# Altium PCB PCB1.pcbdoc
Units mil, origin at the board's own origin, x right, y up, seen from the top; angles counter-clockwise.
Board outline 2295 x 2720 mil, 4 copper layers (Top Layer, GND, PWR, Bottom Layer), stack 62.5 mil thick; 57 components, 63 nets, 259 pads, 97 vias.
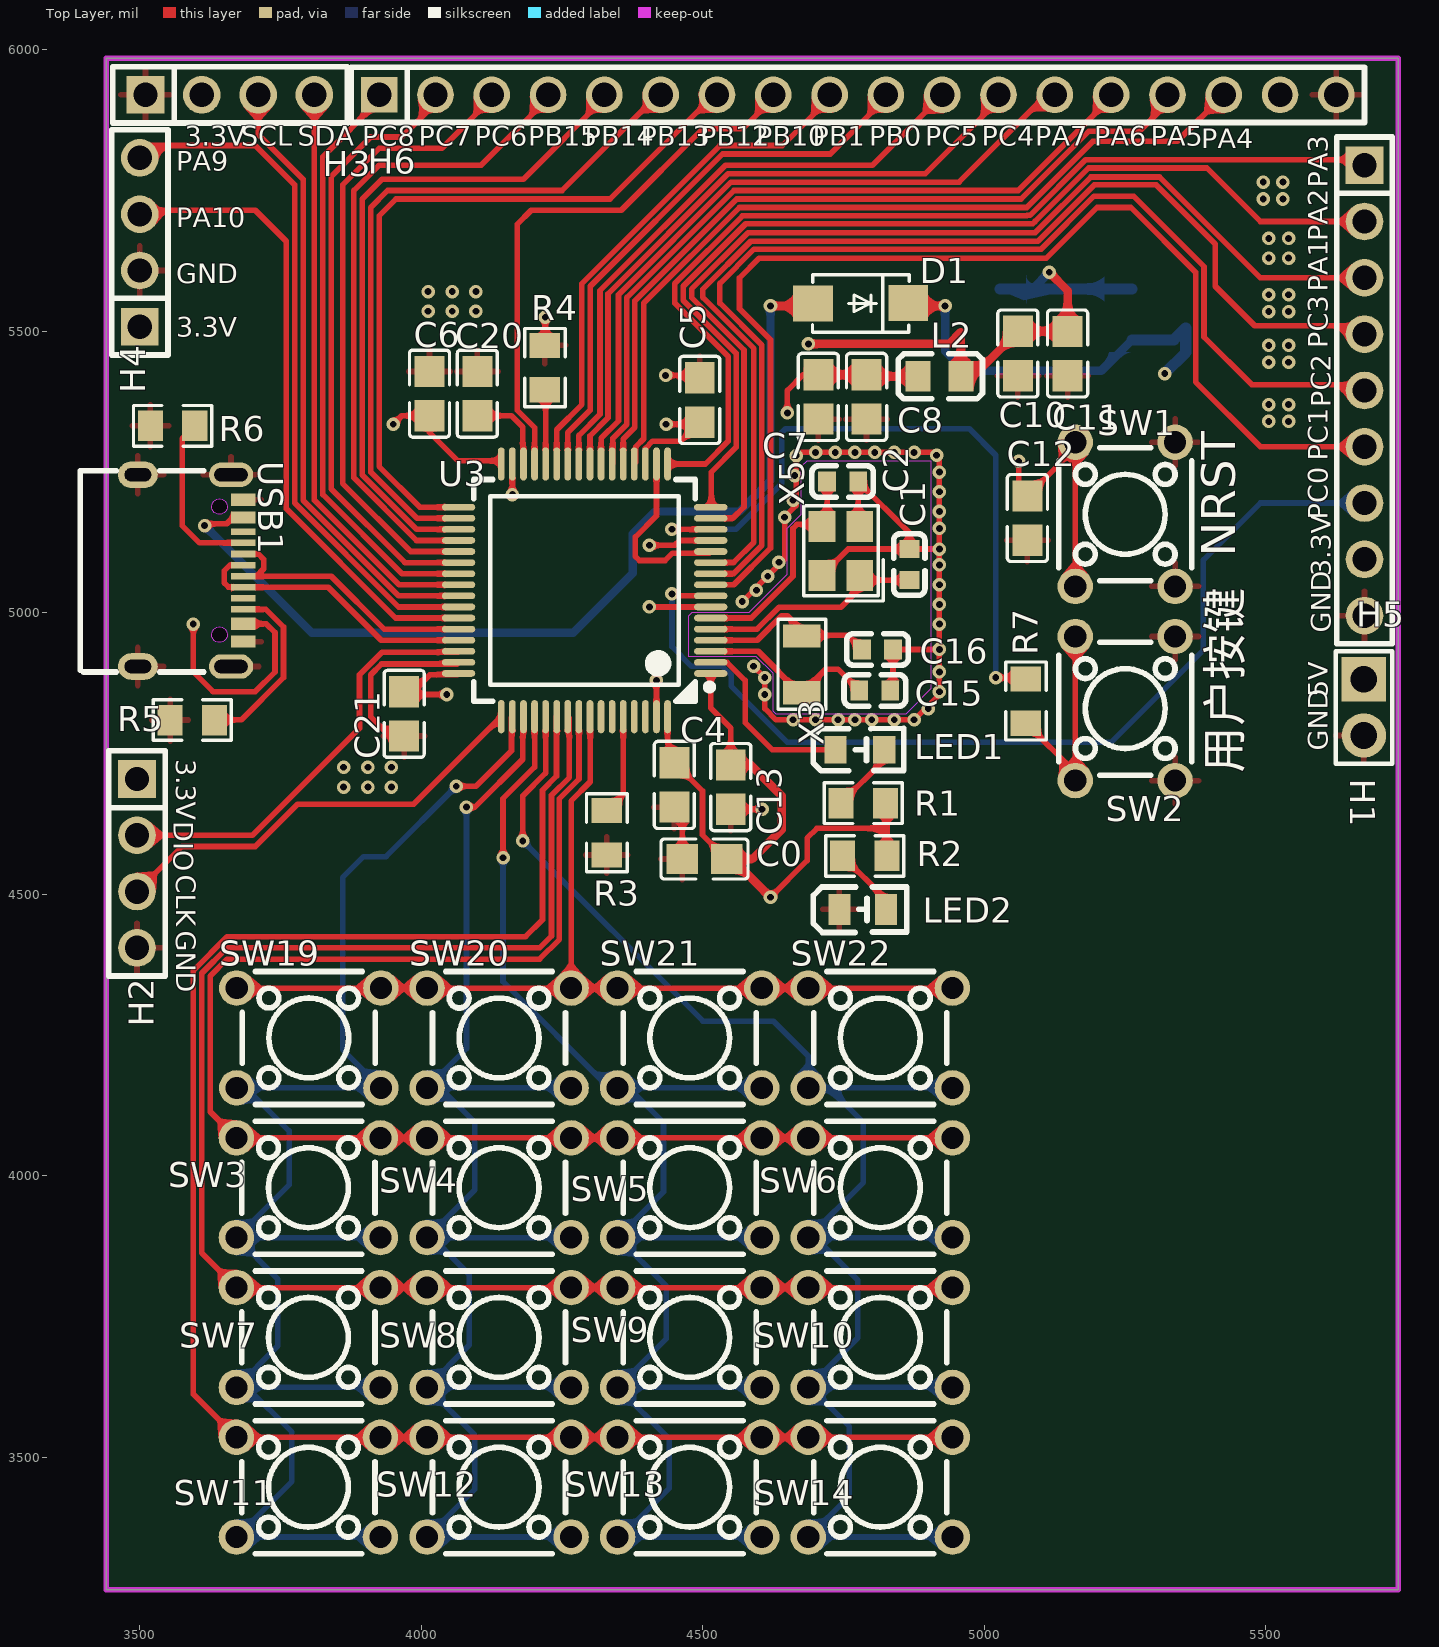
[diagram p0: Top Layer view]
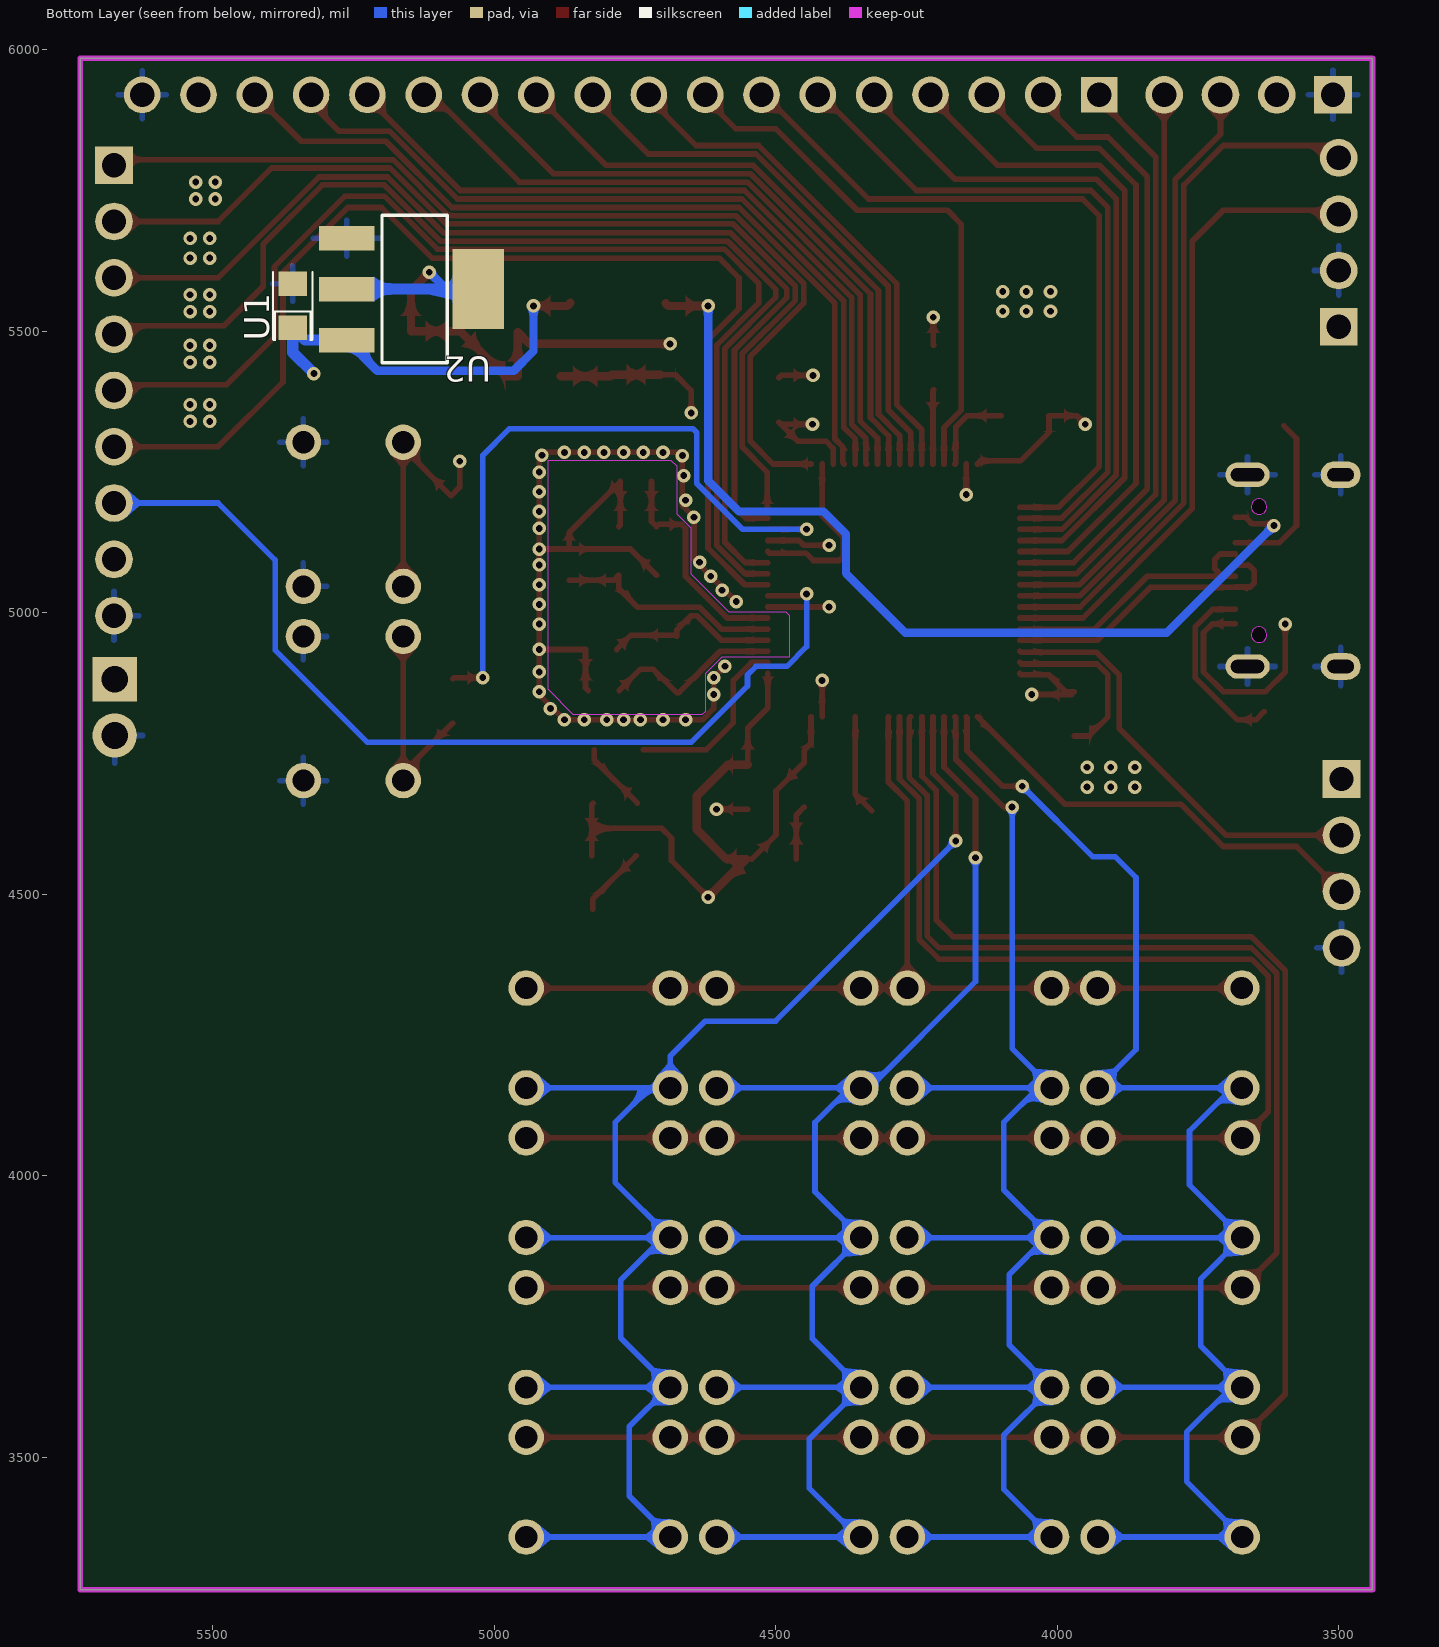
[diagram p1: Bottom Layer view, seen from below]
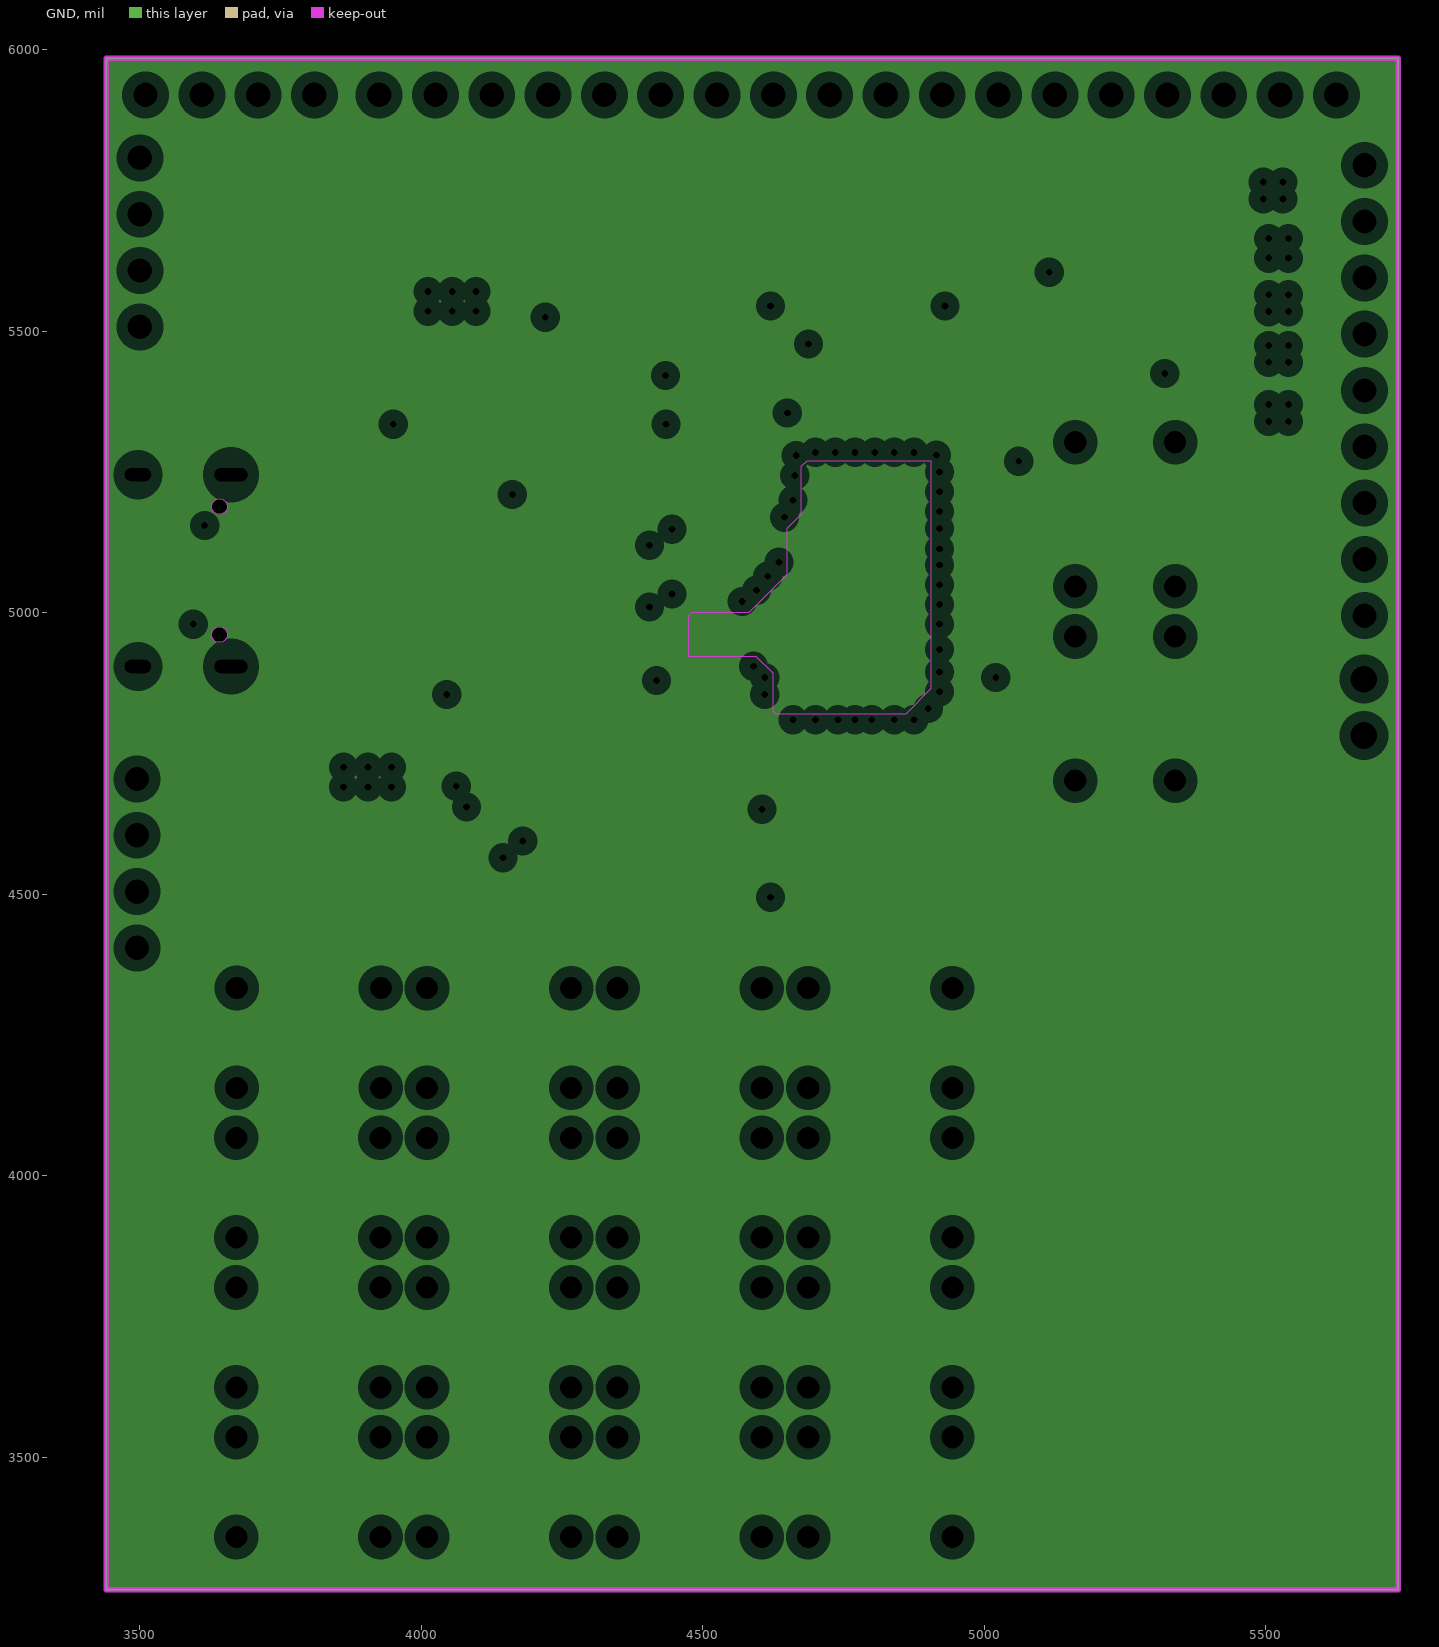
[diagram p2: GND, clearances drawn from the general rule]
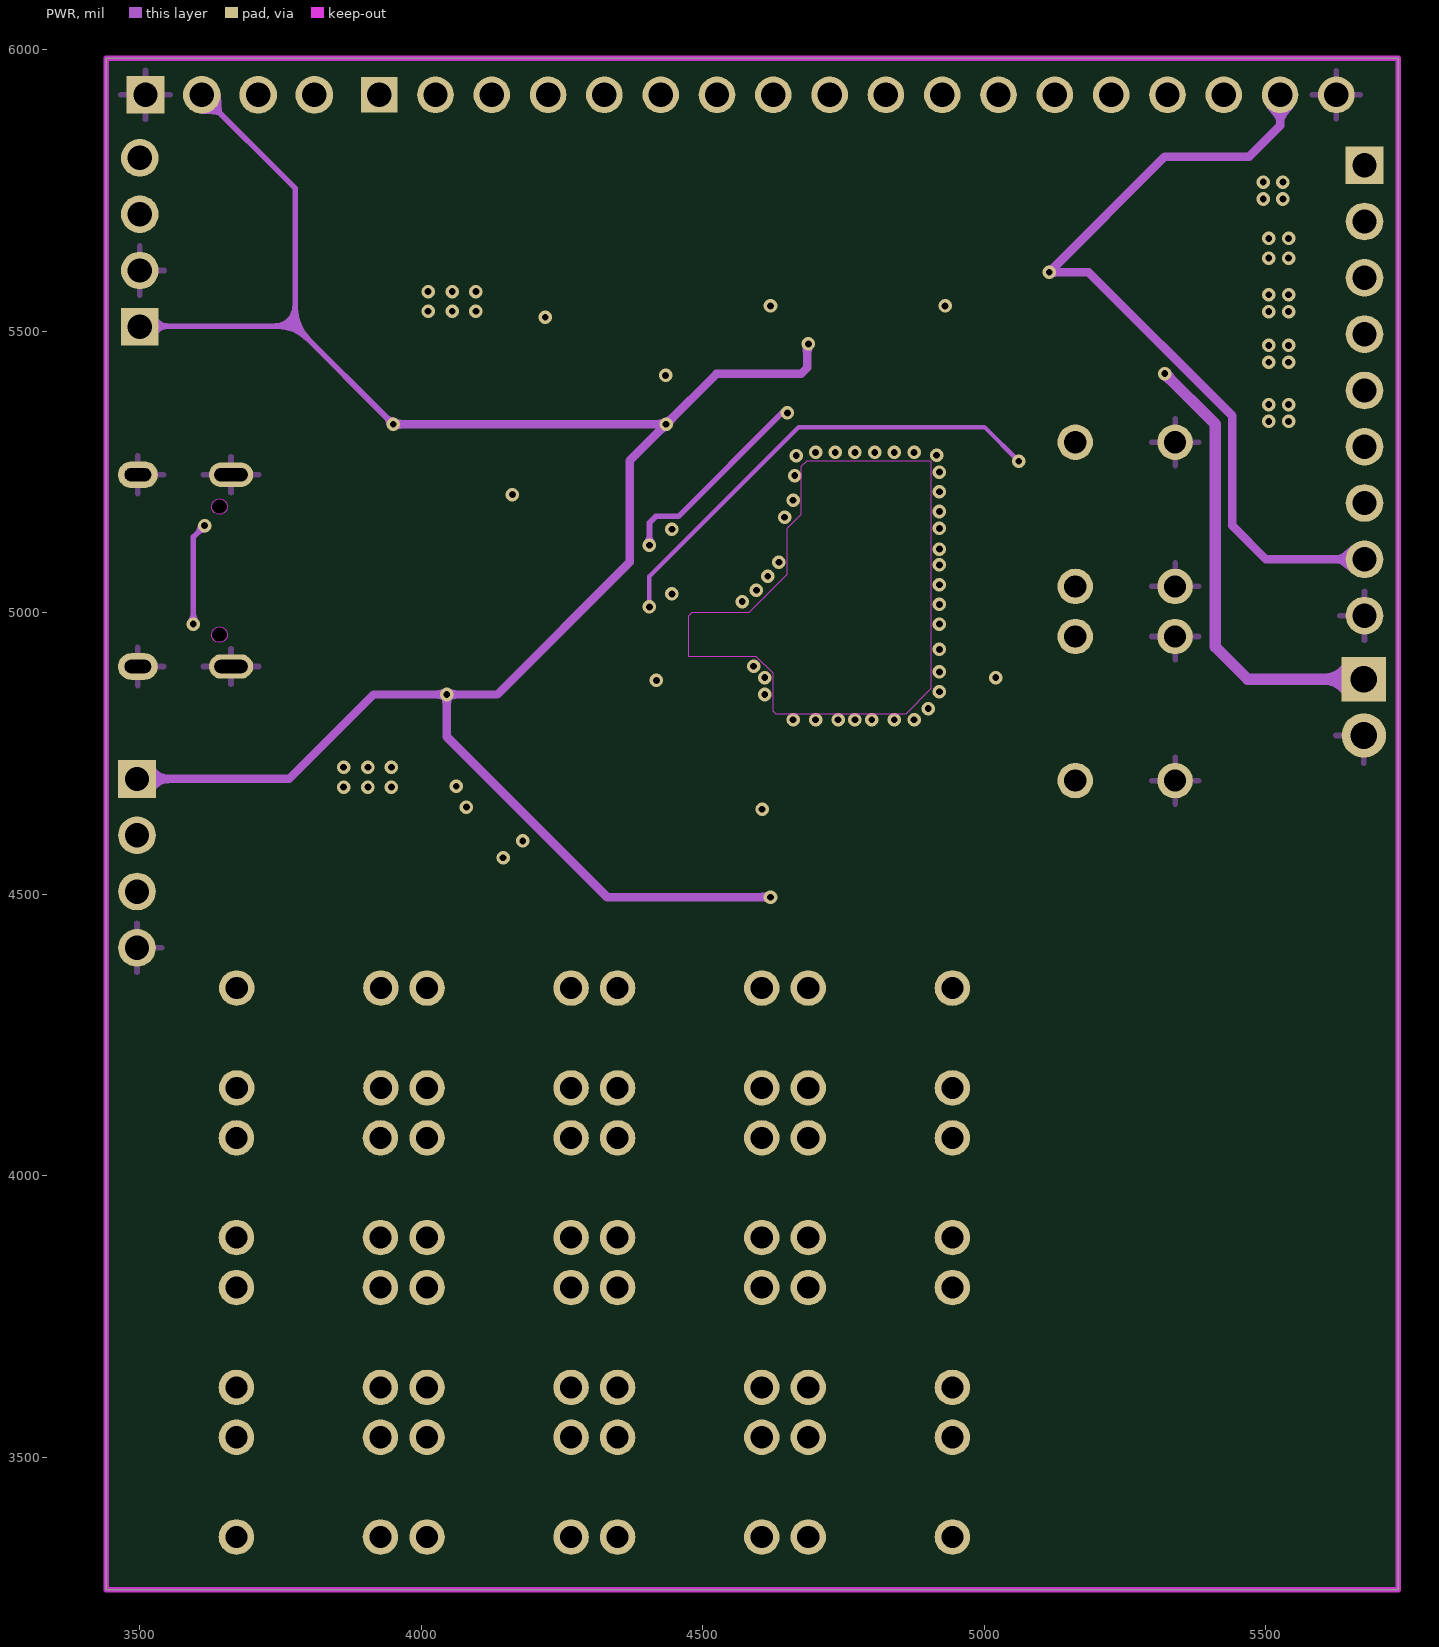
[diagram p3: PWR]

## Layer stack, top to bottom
Top Layer: signal copper 1.4
Dielectric1: surface 8.3, 7628 RC49% 8.6mil, Dk 0
GND: plane copper 0.6
Dielectric2: surface 41.9, 1.1mm H/HOZ Copper, Dk 0
PWR: signal copper 0.6
Dielectric3: surface 8.3, 7628 RC49% 8.6mil, Dk 0
Bottom Layer: signal copper 1.4

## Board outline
3440,5985 3440,3265 5735,3265 5735,5985

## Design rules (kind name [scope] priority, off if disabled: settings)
BoardOutlineClearance copperThickness1oz [All] p0: genericclearance=10 ignorepadtopadclearanceinfootprint=FALSE except(0: Arc-SplitContinuation Track-SplitContinuation SMDPad-SplitContinuation THPad-SplitContinuation Via-SplitContinuation Fill-SplitContinuation Poly-SplitContinuation Region-SplitContinuation Text-SplitContinuation)
BoardOutlineClearance copperThickness2oz [All] p0: genericclearance=10 ignorepadtopadclearanceinfootprint=FALSE except(0: Arc-SplitContinuation Track-SplitContinuation SMDPad-SplitContinuation THPad-SplitContinuation Via-SplitContinuation Fill-SplitContinuation Poly-SplitContinuation Region-SplitContinuation Text-SplitContinuation)
BoardOutlineClearance otherClearance [All] p0: genericclearance=10 ignorepadtopadclearanceinfootprint=FALSE except(0: Arc-SplitContinuation Track-SplitContinuation SMDPad-SplitContinuation THPad-SplitContinuation Via-SplitContinuation Fill-SplitContinuation Poly-SplitContinuation Region-SplitContinuation Text-SplitContinuation)
Clearance copperThickness1oz [All] p1: gap=7 ignorepadtopadclearanceinfootprint=FALSE
Clearance copperThickness2oz [All] p1: gap=7 ignorepadtopadclearanceinfootprint=FALSE
Clearance otherClearance [All] p1: gap=7 ignorepadtopadclearanceinfootprint=FALSE
DiffPairsRouting differentialPair [All] p1: maxuncoupledlength=10 minlimit=6 maxlimit=Infinity mostfreqgap=6 toplayer_minwidth=5 toplayer_prefwidth=10 toplayer_maxwidth=100 bottomlayer_minwidth=5 bottomlayer_prefwidth=10 bottomlayer_maxwidth=100 midlayer1_minwidth=5 midlayer1_prefwidth=10 midlayer1_maxwidth=100
PasteMaskExpansion pasteMaskExpansion [All] p1: expansion=0
PlaneConnect innerPlane [All] p1: planeconnectstyle=Relief reliefexpansion=20 reliefentries=4 reliefconductorwidth=10 reliefairgap=10
PolygonConnect copperRegion [All] p1: connectstyle=Relief reliefentries=4 reliefconductorwidth=10 polygonreliefangle="90 Angle" airgapwidth=10
RoutingVias viaSize [All] p1: viastyle="Through Hole" holewidth=12.0078 minholewidth=11.811 maxholewidth=248.0314 width=12.0078 minwidth=11.811 maxwidth=248.0314
SolderMaskExpansion solderMaskExpansion [IsVia] p1: useseparateexpansions=TRUE expansion=-1000 expansionbottom=-1000
SolderMaskExpansion solderMaskExpansion [All] p2: useseparateexpansions=TRUE expansion=2 expansionbottom=2
Width copperThickness1oz [All] p1: maxlimit=100 minlimit=5 preferedwidth=10
Width copperThickness2oz [All] p1: maxlimit=100 minlimit=8 preferedwidth=10

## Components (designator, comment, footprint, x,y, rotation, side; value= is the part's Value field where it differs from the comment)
C0 "4.7uF" C0805#1 4502.8,4562.8 r0 top
C1 "8pF" C0603#1 4866.5,5085.7 r270 top
C2 "8pF" C0603#2 4748.1,5233.3 r180 top
C4 "100nF" C0805#2 4449.4,4694.4 r90 top
C5 "100nF" C0805#1 4494.4,5378.1 r270 top
C6 "100nF" C0805#3 4014.4,5389.4 r270 top
C7 "100nF" C0805#2 4705,5383.5 r90 top
C8 "1uF" C0805#2 4790.6,5383.5 r90 top
C10 "100nF" C0805#3 5059.4,5460.6 r90 top
C11 "10uF" C0805#2 5147.6,5460.6 r90 top
C12 "100nF" C0805#2 5076.3,5168.4 r90 top
C13 "100nF" C0805#3 4549.4,4690.6 r90 top
C15 "1.5pF" C0603#1 4805.3,4862.2 r180 top
C16 "1.5pF" C0603#2 4810,4935 r180 top
C20 "4.7uF" C0805#3 4099.4,5389.4 r270 top
C21 "100nF" C0805#3 3969.4,4820.6 r90 top
D1 "SS14" SMA_L4.3-W2.6-LS5.0-FD 4780,5550 r0 top
H1 "PZ254V-11-02P" HDR-TH_2P-P2.54-V-M 5673.8,4832.2 r270 top
H2 "PZ254V-11-04P" HDR-TH_4P-P2.54-V-M 3495,4555 r270 top
H3 "PM254V-11-04-H85" HDR-TH_4P-P2.54-V-F 3660,5920 r0 top
H4 "PZ254V-11-04P" HDR-TH_4P-P2.54-V-M 3499.9,5658 r90 top
H5 "PZ254V-11-09P" HDR-TH_9P-P2.54-V-M 5675,5395 r270 top
H6 "PZ254-1-18-Z-8.5" HDR-TH_18P-P2.54-V-M 4775,5920 r0 top
L2 "CBW201209U102T" L0805 4920,5420 r180 top
LED1 "GL0805UB01" LED0805-RD_BLUE 4778.7,4757 r0 top
LED2 "GL0805UR01" LED0805-R-RD_RED 4783.7,4473.3 r0 top
R1 "1.5kΩ" R0805#1 4784.9,4662 r180 top
R2 "5.1kΩ" R0805#2 4787.4,4568.3 r180 top
R3 "10kΩ" R0805#1 4329.4,4609.4 r270 top
R4 "10kΩ" R0805#1 4219.4,5435.6 r90 top
R5 "5.1kΩ" R0805#1 3593,4809.6 r0 top
R6 "5.1kΩ" R0805#3 3558,5332.1 r180 top
R7 "330Ω" R0805#2 5073.6,4843.4 r270 top
SW1 "SH-6X6X4.3H-CJ" SW-TH_SH-6X6X4.3H-CJ#1 5250,5175 r90 top
SW2 "SH-6X6X4.3H-CJ" SW-TH_SH-6X6X4.3H-CJ#1 5250,4830 r90 top
SW3 "SH-6X6X4.3H-CJ" SW-TH_SH-6X6X4.3H-CJ#2 3799.3,3979 r0 top
SW4 "SH-6X6X4.3H-CJ" SW-TH_SH-6X6X4.3H-CJ#2 4137.9,3979 r0 top
SW5 "SH-6X6X4.3H-CJ" SW-TH_SH-6X6X4.3H-CJ#3 4476.5,3979 r0 top
SW6 "SH-6X6X4.3H-CJ" SW-TH_SH-6X6X4.3H-CJ#4 4815.1,3979 r0 top
SW7 "SH-6X6X4.3H-CJ" SW-TH_SH-6X6X4.3H-CJ#5 3799.3,3713.1 r0 top
SW8 "SH-6X6X4.3H-CJ" SW-TH_SH-6X6X4.3H-CJ#5 4137.9,3713.1 r0 top
SW9 "SH-6X6X4.3H-CJ" SW-TH_SH-6X6X4.3H-CJ#1 4476.5,3713.1 r0 top
SW10 "SH-6X6X4.3H-CJ" SW-TH_SH-6X6X4.3H-CJ#6 4815.1,3713.1 r0 top
SW11 "SH-6X6X4.3H-CJ" SW-TH_SH-6X6X4.3H-CJ#5 3799.3,3447.2 r0 top
SW12 "SH-6X6X4.3H-CJ" SW-TH_SH-6X6X4.3H-CJ#5 4137.9,3447.2 r0 top
SW13 "SH-6X6X4.3H-CJ" SW-TH_SH-6X6X4.3H-CJ#1 4476.5,3447.2 r0 top
SW14 "SH-6X6X4.3H-CJ" SW-TH_SH-6X6X4.3H-CJ#6 4815.1,3447.2 r0 top
SW19 "SH-6X6X4.3H-CJ" SW-TH_SH-6X6X4.3H-CJ#1 3800,4245 r0 top
SW20 "SH-6X6X4.3H-CJ" SW-TH_SH-6X6X4.3H-CJ#2 4137.9,4244.9 r0 top
SW21 "SH-6X6X4.3H-CJ" SW-TH_SH-6X6X4.3H-CJ#3 4476.5,4244.9 r0 top
SW22 "SH-6X6X4.3H-CJ" SW-TH_SH-6X6X4.3H-CJ#4 4815.1,4244.9 r0 top
U1 "10uF" CAP-SMD_L2.0-W1.3-FD 5357.6,5545.5 r90 bottom
U2 "AMS1117-3.3" SOT-223-3_L6.5-W3.4-P2.30-LS7.0-BR 5145,5575 r0 bottom
U3 "STM32F411RET6" LQFP-64_L10.0-W10.0-P0.50-LS12.0-BL 4290,5040 r90 top locked
USB1 "TYPE-C 16PIN 2MD(073)" USB-C-SMD_TYPE-C-16PIN-2MD-073 3590,5075 r270 top locked
X3 "32.768kHz" CRYSTAL-SMD_L3.2-W1.5-1 4675.8,4908.5 r270 top
X5 "25MHz" CRYSTAL-SMD_4P-L3.2-W2.5-BL 4745,5110 r90 top

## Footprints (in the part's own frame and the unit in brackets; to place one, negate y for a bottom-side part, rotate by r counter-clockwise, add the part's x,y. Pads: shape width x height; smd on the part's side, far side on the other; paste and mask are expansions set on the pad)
C0603#1 [mil]
  rect 31.5x35.4 smd: 1(-27.6,0) 2(27.5,0)
  silkscreen extent -55,-28 55,28
C0603#2 [mil]
  rect 31.5x35.4 smd: 1(-27.6,0) 2(27.6,0)
  silkscreen extent -55,-28 55,28
C0805#1 [mil]
  rect 55.5x53.1 smd paste-3937 mask+2: 1(-39.4,0) 2(39.4,0)
  silkscreen extent -77,-36 77,36
C0805#2 [mil]
  rect 55.5x53.1 smd paste-3937 mask+2: 1(-39.4,0) 2(39.3,0)
  silkscreen extent -77,-36 77,36
C0805#3 [mil]
  rect 55.5x53.1 smd paste-3937 mask+2: 1(-39.3,0) 2(39.4,0)
  silkscreen extent -77,-36 77,36
CAP-SMD_L2.0-W1.3-FD [mil]
  rect 43.3x51.2 smd paste+0 mask+2: 1(-39.4,0) 2(39.3,0)
  silkscreen extent -62,-35 60,35
CRYSTAL-SMD_4P-L3.2-W2.5-BL [mil]
  rect 55.1x47.2 smd: 1(-43.3,-33.5) 2(43.3,-33.5) 3(43.3,33.5) 4(-43.3,33.5)
  silkscreen extent -89,-75 80,66
CRYSTAL-SMD_L3.2-W1.5-1 [mil]
  rect 41.3x66.9 smd: 1(-50.2,0) 2(50.2,0)
  silkscreen extent -80,-43 80,42
HDR-TH_2P-P2.54-V-M [mil]
  rect 78.7x78.7 hole 47.2: 1(-50,0)
  round 78.7 hole 47.2: 2(50,0)
  silkscreen extent -100,-50 100,50
HDR-TH_4P-P2.54-V-F [mil]
  rect 66.9x66.9 hole 43.3: 1(-150,0)
  round 66.9 hole 43.3: 2(-50,0) 3(50,0) 4(150,0)
  silkscreen extent -208,-50 208,50
HDR-TH_4P-P2.54-V-M [mil]
  rect 66.9x66.9 hole 43.3: 1(-150,0)
  round 66.9 hole 43.3: 2(-50,0) 3(50,0) 4(150,0)
  silkscreen extent -200,-50 200,50
HDR-TH_9P-P2.54-V-M [mil]
  rect 66.9x66.9 hole 43.3: 1(-400,0)
  round 66.9 hole 43.3: 2(-300,0) 3(-200,0) 4(-100,0) 5(0,0) 6(100,0) 7(200,0) 8(300,0) 9(400,0)
  silkscreen extent -450,-49 450,49
HDR-TH_18P-P2.54-V-M [mil]
  rect 65x63 hole 43.3: 1(-850,0)
  round 65 hole 43.3: 2(-750,0) 3(-650,0) 4(-550,0) 5(-450,0) 6(-350,0) 7(-250,0) 8(-150,0) 9(-50,0) 10(50,0) 11(150,0) 12(250,0) 13(350,0) 14(450,0) 15(550,0) 16(650,0) 17(750,0) 18(850,0)
  silkscreen extent -900,-49 900,49
L0805 [mil]
  rect 44.6x54.2 smd paste-3937 mask+2: 1(-38,0) 2(38,0)
  silkscreen extent -77,-40 73,40
LED0805-R-RD_RED [mil]
  rect 39.4x55.1 smd: 1(41.3,0) 2(-41.4,0)
  silkscreen extent -88,-41 78,40
LED0805-RD_BLUE [mil]
  rect 39.4x49.2 smd: 1(-43.3,0) 2(43.3,0)
  silkscreen extent -83,-37 78,38
LQFP-64_L10.0-W10.0-P0.50-LS12.0-BL [mil]
  oval 11.8x59.1 smd: 1(-147.6,-223.9) 2(-127.9,-223.9) 3(-108.3,-223.9) 4(-88.6,-223.9) 5(-68.9,-223.9) 6(-49.2,-223.9) 7(-29.5,-223.9) 8(-9.8,-223.9) 9(9.8,-223.9) 10(29.5,-223.9) 11(49.2,-223.9) 12(68.9,-223.9) 13(88.6,-223.9) 14(108.3,-223.9) 15(127.9,-223.9) 16(147.6,-223.9) 33(147.6,223.9) 34(127.9,223.9) 35(108.3,223.9) 36(88.6,223.9) 37(68.9,223.9) 38(49.2,223.9) 39(29.5,223.9) 40(9.8,223.9) 41(-9.8,223.9) 42(-29.5,223.9) 43(-49.2,223.9) 44(-68.9,223.9) 45(-88.6,223.9) 46(-108.3,223.9) 47(-127.9,223.9) 48(-147.6,223.9)
  oval 59.1x11.8 smd: 17(224.4,-147.2) 18(224.4,-127.5) 19(224.4,-107.8) 20(224.4,-88.1) 21(224.4,-68.4) 22(224.4,-48.7) 23(224.4,-29.1) 24(224.4,-9.4) 25(224.4,10.3) 26(224.4,30) 27(224.4,49.7) 28(224.4,69.4) 29(224.4,89) 30(224.4,108.7) 31(224.4,128.4) 32(224.4,148.1) 49(-224.4,148.1) 50(-224.4,128.4) 51(-224.4,108.7) 52(-224.4,89) 53(-224.4,69.4) 54(-224.4,49.7) 55(-224.4,30) 56(-224.4,10.3) 57(-224.4,-9.4) 58(-224.4,-29.1) 59(-224.4,-48.7) 60(-224.4,-68.4) 61(-224.4,-88.1) 62(-224.4,-107.8) 63(-224.4,-127.5) 64(-224.4,-147.2)
  silkscreen extent -197,-228 197,197
R0805#1 [mil]
  rect 44.6x54.2 smd paste-3937 mask+2: 1(-39.3,0) 2(39.4,0)
  silkscreen extent -69,-36 69,36
R0805#2 [mil]
  rect 44.6x54.2 smd paste-3937 mask+2: 1(-39.4,0) 2(39.4,0)
  silkscreen extent -69,-36 69,36
R0805#3 [mil]
  rect 44.6x54.2 smd paste-3937 mask+2: 1(-39.4,0) 2(39.3,0)
  silkscreen extent -69,-36 69,36
SMA_L4.3-W2.6-LS5.0-FD [mil]
  rect 70.9x63.8 smd: 1(-84.6,-0.4) 2(84.6,0.4)
  silkscreen extent -85,-52 86,51
SOT-223-3_L6.5-W3.4-P2.30-LS7.0-BR [mil]
  rect 98.4x43.3 smd: 1(116.9,-90.6) 2(116.9,0) 3(116.9,90.6)
  rect 92.1x141.7 smd: 4(-116.9,0)
  silkscreen extent -62,-131 54,131
SW-TH_SH-6X6X4.3H-CJ#1 [mil]
  round 63 hole 39.4: A(-128,88.6) B(128,88.6) C(-128,-88.6) D(128,-88.6)
  silkscreen extent -118,-118 118,118
SW-TH_SH-6X6X4.3H-CJ#2 [mil]
  round 63 hole 39.4: A(-127.9,88.6) B(128,88.6) C(-127.9,-88.5) D(128,-88.5)
  silkscreen extent -118,-118 118,118
SW-TH_SH-6X6X4.3H-CJ#3 [mil]
  round 63 hole 39.4: A(-128,88.6) B(128,88.6) C(-128,-88.5) D(128,-88.5)
  silkscreen extent -118,-118 118,118
SW-TH_SH-6X6X4.3H-CJ#4 [mil]
  round 63 hole 39.4: A(-128,88.6) B(127.9,88.6) C(-128,-88.5) D(127.9,-88.5)
  silkscreen extent -118,-118 118,118
SW-TH_SH-6X6X4.3H-CJ#5 [mil]
  round 63 hole 39.4: A(-127.9,88.6) B(128,88.6) C(-127.9,-88.6) D(128,-88.6)
  silkscreen extent -118,-118 118,118
SW-TH_SH-6X6X4.3H-CJ#6 [mil]
  round 63 hole 39.4: A(-128,88.6) B(127.9,88.6) C(-128,-88.6) D(127.9,-88.6)
  silkscreen extent -118,-118 118,118
USB-C-SMD_TYPE-C-16PIN-2MD-073 [mil]
  oval 43.3x78.7 hole 23.6 slot 59.1 at 90 deg paste+0 mask+2: 13(-170.3,71.9) 14(170.3,71.9)
  oval 47.2x70.9 hole 23.6 slot 47.2 at 90 deg paste+0 mask+2: 13(-170.3,-93.5) 14(170.3,-93.5)
  rect 21.7x43.3 smd paste-3937 mask+2: A1B12(-126,93.5) A4B9(-94.5,93.5) B1A12(126,93.5) B4A9(94.5,93.5)
  rect 11.8x43.3 smd paste-3937 mask+2: A5(-49.2,93.5) A6(-9.8,93.5) A7(9.8,93.5) A8(49.2,93.5) B5(68.9,93.5) B6(29.5,93.5) B7(-29.5,93.5) B8(-68.9,93.5)
  Board Outline Layer lines w0.1: 113,37.6 116.2,37.8 119.2,38.7 122,40.3 124.3,42.5 126.1,45.2 127.2,48.2 127.6,51.4 127.2,54.6 126.1,57.6 124.3,60.2 122,62.4 119.2,64 116.2,64.9 113,65.1 109.8,64.6 106.9,63.3 104.3,61.4 102.3,58.9 100.8,56.1 100.1,53 100.1,49.8 100.8,46.7 102.3,43.8 104.3,41.4 106.9,39.4 109.8,38.2 113,37.6 ; -114.6,37.6 -111.4,37.8 -108.3,38.7 -105.5,40.3 -103.2,42.5 -101.5,45.2 -100.4,48.2 -100,51.4 -100.4,54.6 -101.5,57.6 -103.2,60.2 -105.5,62.4 -108.3,64 -111.4,64.9 -114.6,65.1 -117.7,64.6 -120.7,63.3 -123.2,61.4 -125.3,58.9 -126.7,56.1 -127.5,53 -127.5,49.8 -126.7,46.7 -125.3,43.8 -123.2,41.4 -120.7,39.4 -117.7,38.2 -114.6,37.6
  Board Outline Layer region: -100,51.4 -100.4,48.2 -101.5,45.2 -103.2,42.5 -105.5,40.3 -108.3,38.7 -111.4,37.8 -114.6,37.6 -117.7,38.2 -120.7,39.4 -123.2,41.4 -125.3,43.8 -126.7,46.7 -127.5,49.8 -127.5,53 -126.7,56.1 -125.3,58.9 -123.2,61.4 -120.7,63.3 -117.7,64.6 -114.6,65.1 -111.4,64.9 -108.3,64 -105.5,62.4 -103.2,60.2 -101.5,57.6 -100.4,54.6
  Board Outline Layer region: -100,51.4 -100.4,48.2 -101.5,45.2 -103.2,42.5 -105.5,40.3 -108.3,38.7 -111.4,37.8 -114.6,37.6 -117.7,38.2 -120.7,39.4 -123.2,41.4 -125.3,43.8 -126.7,46.7 -127.5,49.8 -127.5,53 -126.7,56.1 -125.3,58.9 -123.2,61.4 -120.7,63.3 -117.7,64.6 -114.6,65.1 -111.4,64.9 -108.3,64 -105.5,62.4 -103.2,60.2 -101.5,57.6 -100.4,54.6
  Board Outline Layer region: 127.6,51.4 127.2,48.2 126.1,45.2 124.3,42.5 122,40.3 119.2,38.7 116.2,37.8 113,37.6 109.8,38.2 106.9,39.4 104.3,41.4 102.3,43.8 100.8,46.7 100.1,49.8 100.1,53 100.8,56.1 102.3,58.9 104.3,61.4 106.9,63.3 109.8,64.6 113,65.1 116.2,64.9 119.2,64 122,62.4 124.3,60.2 126.1,57.6 127.2,54.6
  Board Outline Layer region: 127.6,51.4 127.2,48.2 126.1,45.2 124.3,42.5 122,40.3 119.2,38.7 116.2,37.8 113,37.6 109.8,38.2 106.9,39.4 104.3,41.4 102.3,43.8 100.8,46.7 100.1,49.8 100.1,53 100.8,56.1 102.3,58.9 104.3,61.4 106.9,63.3 109.8,64.6 113,65.1 116.2,64.9 119.2,64 122,62.4 124.3,60.2 126.1,57.6 127.2,54.6
  Multi-Layer board cut-out: -100,51.4 -100.4,48.2 -101.5,45.2 -103.2,42.5 -105.5,40.3 -108.3,38.7 -111.4,37.8 -114.6,37.6 -117.7,38.2 -120.7,39.4 -123.2,41.4 -125.3,43.8 -126.7,46.7 -127.5,49.8 -127.5,53 -126.7,56.1 -125.3,58.9 -123.2,61.4 -120.7,63.3 -117.7,64.6 -114.6,65.1 -111.4,64.9 -108.3,64 -105.5,62.4 -103.2,60.2 -101.5,57.6 -100.4,54.6
  Multi-Layer board cut-out: 127.6,51.4 127.2,48.2 126.1,45.2 124.3,42.5 122,40.3 119.2,38.7 116.2,37.8 113,37.6 109.8,38.2 106.9,39.4 104.3,41.4 102.3,43.8 100.8,46.7 100.1,49.8 100.1,53 100.8,56.1 102.3,58.9 104.3,61.4 106.9,63.3 109.8,64.6 113,65.1 116.2,64.9 119.2,64 122,62.4 124.3,60.2 126.1,57.6 127.2,54.6
  silkscreen extent -177,-196 180,24

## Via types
v1: diameter 24, hole 12, Top Layer to Bottom Layer, 97 vias

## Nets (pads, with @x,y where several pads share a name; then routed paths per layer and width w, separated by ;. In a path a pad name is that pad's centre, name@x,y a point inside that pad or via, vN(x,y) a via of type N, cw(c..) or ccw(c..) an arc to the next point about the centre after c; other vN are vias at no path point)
3.3V: C0.2 C4.2 C5.2 C6.2 C10.2 C11.2 C13.2 C21.2 H2.1 H3.2 H4.1 H5.8 H6.17 L2.1 R1.1 R2.1 U2.2 U2.4 U3.1 U3.19 U3.32 U3.48 U3.64 | length 8196.4
  Top Layer w10: v1(3950,5335) 3965,5350 C6.2 4014.4,5320.6 4065,5270 4136.3,5270 U3.32 ; v1(4045,4855) 3974.4,4855 C21.2 3985,4860 4015,4890 4063.7,4890 U3.48 ; U3.19 4397.8,5292.2 4410.5,5304.9 4460.6,5304.9 C5.2@4490.6,5335 ; v1(4434.5,5335) C5.2@4490.6,5335 ; U3.64 4437.2,4767.8 4449.4,4755.6 C4.2 4499.3,4683.8 4499.3,4605.7 C0.2 ; C5.2 C5.2@4490.6,5335 ; U3.1 4513.9,4831.1 4549.4,4795.6 C13.2 ; v1(4620,4495) 4685,4560 4685,4600 4702.3,4617.3 4826.8,4617.3 ; R1.1 4826.8,4659.5 4826.8,4617.3 ; R2.1 4826.8,4617.3
  Top Layer w15: C13.2 4585,4730 4640,4675 4640,4615 4587.8,4562.8 4552.2,4562.8 v1(4620,4495) ; v1(4687.4,5477.6) 4937,5477.6 4958,5498.7 L2.1 4979.4,5420 C10.2 ; C10.2@5059.4,5499.9 C11.2 5147.6,5572.4 v1(5115,5605)
  PWR w10: H4.1 3501.2,5509.3 3775.7,5509.3 ; H3.2 3775.7,5754.3 3775.7,5509.3 ; v1(3950,5335) 3775.7,5509.3
  PWR w15: H2.1 3765,4705 3915,4855 v1(4045,4855) ; v1(3950,5335) v1(4434.5,5335) ; v1(4620,4495) 4330,4495 4045,4780 v1(4045,4855) ; v1(4687.4,5477.6) 4685,5475.2 4685,5435 4674.4,5424.4 4523.9,5424.4 v1(4434.5,5335) ; H6.17 5525,5865 5470,5810 5320,5810 v1(5115,5605) 5185,5605 5440,5350 5440,5155 5500,5095 H5.8 ; v1(4045,4855) 4135,4855 4370,5090 4370,5270.5 v1(4434.5,5335)
  Bottom Layer w15: 5085,5575 v1(5115,5605)
  Bottom Layer w20: U2.4 5085,5575 U2.2
5V: D1.2 H1.1 U1.1 U2.3 | length 1528.3
  Top Layer w15: D1.2 4870,5545 v1(4930,5545)
  PWR w20: v1(5320,5425) 5410,5335 5410,4939.5 5467.3,4882.2 H1.1
  Bottom Layer w15: v1(4930,5545) 4930,5465 4965,5430 5207.5,5430 U2.3
  Bottom Layer w20: U2.3 5336,5484.4 U1.1 5357.6,5462.6 v1(5320,5425)
$1N58: LED1.2 R1.2 | length 126.7
  Top Layer w10: R1.2 4822,4738.5 LED1.2
$1N62: LED2.1 R2.2 | length 126.9
  Top Layer w10: R2.2 4825,4491.3 LED2.1
$1N82: R5.2 USB1.B5 | length 334.1
  Top Layer w10: R5.2@3632.4,4824.6 3647,4810 3680,4810 3755,4885 3755,4975 3723.9,5006.1 USB1.B5
$1N83: R6.1 USB1.A5 | length 307.6
  Top Layer w10: R6.1 3575,5309.7 3575,5155 3605.8,5124.2 USB1.A5
$1N95: R7.2 SW2.A SW2.B | length 380
  Top Layer w10: R7.2 SW2.A@5161.4,4716.2 ; SW2.A@5161.4,4702.1 SW2.A@5161.4,4716.2 ; SW2.B@5161.4,4957.9 SW2.A@5161.4,4716.2
$1N139: C20.2 U3.30 | length 155
  Top Layer w10: C20.2 4160,5350 4180,5330 4180,5265.7 U3.30
BOOT0: R3.1 U3.60 | length 178.9
  Top Layer w10: R3.1 4358.4,4677.8 U3.60
C1: SW19.A SW19.B SW20.A SW20.B SW21.A SW21.B SW22.A SW22.B U3.57 | length 1767.3
  Top Layer w10: SW19.A@3672.1,4333.6 3927.9,4333.6 4010,4333.6 SW20.B@4265.9,4333.6 ; U3.57 4300,4815 4300,4700 4265.9,4665.9 SW20.B@4265.9,4333.6 ; SW22.B@4943,4333.6 4687.1,4333.6 4604.4,4333.6 4348.6,4333.6 SW20.B@4265.9,4333.6
C2: SW3.A SW3.B SW4.A SW4.B SW5.A SW5.B SW6.A SW6.B U3.56 | length 2635.4
  Top Layer w10: U3.56 4280,4815.3 4280,4705 4245,4670 4245,4420 4210,4385 3655,4385 3625,4355 3625,4114 SW3.A SW3.B SW4.A SW4.B 4348.6,4067.6 4604.4,4067.6 SW6.A SW6.B
C3: SW7.A SW7.B SW8.A SW8.B SW9.A SW9.B SW10.A SW10.B U3.55 | length 2907.6
  Top Layer w10: U3.55 4262.8,4812.8 4262.8,4707.8 4231,4676 4231,4426 4210,4405 3655,4405 3610,4360 3610,3863.1 SW7.A SW7.B SW8.A SW8.B 4348.6,3801.7 4604.4,3801.7 SW10.A SW10.B
C4: SW11.A SW11.B SW12.A SW12.B SW13.A SW13.B SW14.A SW14.B U3.54 | length 3160.7
  Top Layer w10: U3.54 4240,4815.3 4240,4710 4215,4685 4215,4455 4185,4425 3655.2,4425 3595,4364.8 3595,3612.2 SW11.A SW11.B SW12.A SW12.B 4348.6,3535.8 4604.4,3535.8 SW14.A SW14.B
GND: C0.1 C1.1 C2.1 C4.1 C5.1 C6.1 C7.1 C8.1 C10.1 C11.1 C12.1 C13.1 C15.1 C16.1 C20.1 C21.1 H1.2 H2.4 H3.1 H4.2 H5.9 H6.18 LED2.2 R3.2 R4.2 R5.1 R6.2 SW1.C SW1.D SW2.C SW2.D U1.2 U2.1 U3.12 U3.18 U3.31 U3.47 U3.63 USB1.13 USB1.14 USB1.A1B12 USB1.B1A12 X5.2 X5.4 | length 3046
  Top Layer w10: C21.1 3943.7,4781.3 3910,4815 3910,4890 3929.2,4909.2 4063.3,4909.2 U3.47 ; v1(4161.6,5210) U3.31 ; R4.2 4220,5475.6 v1(4220,5525) ; U3.63 v1(4417.5,4880) ; U3.18 4417.5,5172.5 4380,5135 4380,5100 4387.1,5092.9 4432.9,5092.9 4446,5106 4483.2,5106 4483.3,5106.1 4511.1,5106.1 U3.12 ; v1(4433.6,5421.7) 4490.2,5421.7 C5.1 ; C4.1 4463.4,4641 C0.1 ; C13.1 v1(4605,4651.3) ; v1(4570,5020) v1(4615,5065) 4645,5095 v1(4645,5170) 4665.6,5190.6 v1(4665.6,5279.4) 4671.1,5285 v1(4700,5285) v1(4735,5285) v1(4770,5285) v1(4805,5285) v1(4840,5285) v1(4875,5285) 4910,5285 v1(4915,5280) 4920,5275 v1(4920,5250) v1(4920,5215) v1(4920,5180) v1(4920,5150) v1(4920,5113.3) ; v1(4590,4905) v1(4610,4885) v1(4610,4855) 4610,4830 4630,4810 v1(4660,4810) v1(4700,4810) v1(4740,4810) v1(4770,4810) v1(4800,4810) v1(4840,4810) v1(4875,4810) 4920,4855 v1(4920,4860) v1(4920,4895) v1(4920,4935) ; X5.4 4758.1,5113.3 C1.1 ; X5.2 4775.7,5156.1 C2.1 4866.5,5142.4 C1.1 ; C15.1 4837.6,4866.9 C16.1 v1(4920,4935) ; C1.1 v1(4920,5113.3) ; v1(4920,4935) v1(4920,4980) v1(4920,5015) v1(4920,5050) v1(4920,5085) v1(4920,5113.3)
  other v1: 3861.8,4690.7 3905,4690.7 3946.8,4690.7 3861.8,4725.7 3905,4725.7 3946.8,4725.7 4900,4830 4595,5040 4635,5090 4660,5200 4663,5243.8 5505,5340 5540,5340 5505,5370 5540,5370 5505,5445 5540,5445 5505,5475 5540,5475 5505,5535 5540,5535 4011.8,5535.7 4055,5535.7 4096.8,5535.7 5505,5565 5540,5565 4011.8,5570.7 4055,5570.7 4096.8,5570.7 5505,5630 5540,5630 5505,5665 5540,5665 5495,5735 5530,5735 5495,5765 5530,5765
NRST: C12.2 SW1.A SW1.B U3.7 | length 1398.2
  Top Layer w10: v1(4405,5010.5) U3.7 ; v1(5060.9,5269.1) 5060.9,5223.2 C12.2 SW1.B@5161.4,5292.8 ; SW1.A@5161.4,5047.1 SW1.B@5161.4,5292.8 ; SW1.B@5161.4,5302.9 SW1.B@5161.4,5292.8
  PWR w8: v1(4405,5010.5) 4405,5065 4670,5330 5000,5330 v1(5060.9,5269.1)
PA0: R7.1 U3.14 | length 1239.7
  Top Layer w10: v1(4445,5148.3) U3.14 ; v1(5020,4885) 5071.4,4885 R7.1
  Bottom Layer w10: v1(4445,5148.3) 4558.3,5148.3 4640,5230 4640,5320 4647.1,5327.1 4972.9,5327.1 5020,5280 v1(5020,4885)
PA1: H5.3 U3.15 | length 1844.6
  Top Layer w10: U3.15 4552.9,5167.9 4573,5188 4573,5466.8 4480,5559.8 4480,5575 4580,5675 5090,5675 5189.1,5774.1 5310.9,5774.1 5490,5595 H5.3
PA2: H5.2 U3.16 | length 1786.4
  Top Layer w10: U3.16 4515,5188.7 4515,5250 4559,5294 4559,5460.8 4557.5,5462.3 4557.5,5462.5 4465,5555 4465,5580 4576,5691 5085.6,5691 5089.6,5695 5090,5695 5185,5790 5395,5790 5490,5695 H5.2
PA3: H5.1 U3.17 | length 1764.2
  Top Layer w10: U3.17 4504.4,5264.4 4545,5305 4545,5455 4450,5550 4450,5585 4570,5705 5075,5705 5076,5706 5080.8,5706 5179.8,5805 5665,5805 H5.1
PA4: H6.16 U3.20 | length 1475.9
  Top Layer w10: U3.20 4380.9,5267.2 4380.9,5295.2 4395,5309.3 4395,5550 4565,5720 5075,5720 5192.5,5837.5 5342.5,5837.5 H6.16
PA5: H6.15 U3.21 | length 1403.3
  Top Layer w10: U3.21 4358.4,5308.6 4379,5329.2 4379,5554 4560,5735 5065,5735 5185,5855 5275,5855 5324.9,5904.9 H6.15@5324.9,5918.8
PA6: H6.14 U3.22 | length 1317.3
  Top Layer w10: U3.22 4340,5265.7 4340,5310 4365,5335 4365,5560 4555,5750 5060,5750 5224.9,5914.9 H6.14@5224.9,5918.8
PA7: H6.13 U3.23 | length 1234.8
  Top Layer w10: U3.23 4319.1,5310 4350,5340.9 4350,5565 4550,5765 4955,5765 5108.8,5918.8 H6.13@5124.9,5918.8
PA8: H3.3 U3.41 | length 1099.6
  Top Layer w10: H3.3 3710,5850 3790,5770 3790,5200 3959.8,5030.2 U3.41
PA9: H4.4 U3.42 | length 1245.7
  Top Layer w10: H4.4 3521.9,5830 3705,5830 3775,5760 3775,5195 3959.5,5010.5 U3.42
PA10: H4.3 U3.43 | length 1147.3
  Top Layer w10: H4.3 3506.9,5715 3705,5715 3760,5660 3760,5185 3954.2,4990.8 U3.43
PA11: U3.44 USB1.A7 USB1.B7 | length 520.7
  Top Layer w10: USB1.B7 3710.5,5104.5 3720,5095 3720,5078.2 3706.9,5065.2 USB1.A7 3683.7,5065 3840,5065 3933.9,4971.1 U3.44
PA12: U3.45 USB1.A6 USB1.B6 | length 517.7
  Top Layer w10: USB1.A6 3659.8,5084.8 3650,5075 3650,5053.1 3657.1,5046 3682.9,5046 USB1.B6 3834.5,5045.5 3928.6,4951.4 U3.45
PA13: H2.2 U3.46 | length 762
  Top Layer w10: H2.2 3700,4605 3890,4795 3890,4890 3930,4930 4064.3,4930 U3.46
PA14: H2.3 U3.49 | length 775.6
  Top Layer w10: H2.3 3575,4585 3705,4585 3780,4660 3986.3,4660 U3.49
PA15: SW3.C SW3.D SW7.C SW7.D SW11.C SW11.D SW19.C SW19.D U3.50 | length 2863.5
  Top Layer w10: v1(4062,4692) 4097,4692 4160,4755 4160,4814 U3.50
  Bottom Layer w10: SW7.C 3745,3698.2 3745,3816.9 SW3.C ; SW19.C@3672.1,4156.4 SW19.C@3688.6,4156.4 ; SW11.D SW11.C 3770,3457.2 3770,3545 3690.5,3624.5 SW7.D ; SW3.D SW3.C ; v1(4062,4692) 3937.1,4567.1 3897.1,4567.1 3860,4530 3860,4224.4 3927.9,4156.4 SW19.C@3688.6,4156.4 ; SW3.C 3765,3984.1 3765,4080 SW19.C@3688.6,4156.4
PB0: H6.10 U3.26 | length 1002.4
  Top Layer w10: U3.26 4260,5320 4300,5360 4300,5580 4535,5815 4726.1,5815 H6.10@4829.9,5918.8
PB1: H6.9 U3.27 | length 922.2
  Top Layer w10: U3.27 4240.3,5325.3 4285,5370 4285,5584.8 4530.2,5830 4641.1,5830 H6.9@4729.9,5918.8
PB2: R4.1 U3.28 | length 132.4
  Top Layer w10: R4.1 4220.6,5395 U3.28
PB6: U3.58
PB7: U3.59
PB8: U3.61
PB9: U3.62
PB10: H6.8 U3.29 | length 993.1
  Top Layer w10: U3.29 4201,5329 4170,5360 4170,5690 4195,5715 4355,5715 4500,5860 4571.1,5860 H6.8@4629.9,5918.8
PB12: H6.7 U3.33 | length 1309.5
  Top Layer w10: U3.33 3997.4,5187.6 3925,5260 3925,5705 3955,5735 4335,5735 4518.8,5918.8 H6.7@4529.9,5918.8
PB13: H6.6 U3.34 | length 1262.4
  Top Layer w10: U3.34 3992.1,5167.9 3910,5250 3910,5720 3940,5750 4250,5750 4418.8,5918.8 H6.6@4429.9,5918.8
PB14: H6.5 U3.35 | length 1212.2
  Top Layer w10: U3.35 3991.7,5148.3 3895,5245 3895,5735 3930,5770 4181.1,5770 H6.5@4329.9,5918.8
PB15: H6.4 U3.36 | length 1162.1
  Top Layer w10: U3.36 3991.4,5128.6 3880,5240 3880,5750 3925,5795 4106.1,5795 H6.4@4229.9,5918.8
PC0: H5.7 U3.8 | length 1745.7
  Top Layer w10: v1(4445,5033.5) 4448.3,5030.2 U3.8
  Bottom Layer w10: v1(4445,5033.5) 4445,4940 4480,4905 4535,4905 4550,4890 4550,4870 4650,4770 5225,4770 5388.8,4933.8 5388.8,5093.8 5490,5195 H5.7
PC1: H5.6 U3.9 | length 2087.9
  Top Layer w10: U3.9 4554.8,5049.8 4620,5115 4620,5485 4565,5540 4565,5595 4600,5630 5110,5630 5200,5720 5260,5720 5375,5605 5375,5410 5490,5295 H5.6
PC2: H5.5 U3.10 | length 2032.9
  Top Layer w10: U3.10 4554.5,5069.5 4602.5,5117.5 4602.5,5117.7 4604.4,5119.6 4604.4,5475.6 4530,5550 4530,5585 4591,5646 5100.8,5646 5194.8,5740 5265,5740 5390,5615 5390,5490 5475,5405 5665,5405 H5.5
PC3: H5.4 U3.11 | length 1983.9
  Top Layer w10: U3.11 4554.2,5089.2 4590.4,5125.4 4590.4,5469.6 4500,5560 4500,5575 4585,5660 5095,5660 5195,5760 5305,5760 5410,5655 5410,5580 5480,5510 5660,5510 H5.4
PC4: H6.12 U3.24 | length 1165.4
  Top Layer w10: U3.24 4299.4,5314.4 4330,5345 4330,5345.5 4331.4,5346.8 4331.4,5566.4 4545,5780 4895,5780 H6.12@5035,5920
PC5: H6.11 U3.25 | length 1074.6
  Top Layer w10: U3.25 4279.7,5315 4317.3,5352.7 4317.3,5572.3 4540,5795 4801.1,5795 H6.11@4924.9,5918.8
PC6: H6.3 U3.37 | length 1121.9
  Top Layer w10: U3.37 3981.1,5108.9 3860,5230 3860,5760 3925,5825 4036.1,5825 H6.3@4129.9,5918.8
PC7: H6.2 U3.38 | length 1087.9
  Top Layer w10: H6.2@4024.9,5918.8 4024.9,5904.9 3965,5845 3910,5845 3840,5775 3840,5220 3970.8,5089.2 U3.38
PC8: H6.1 U3.39 | length 1049.5
  Top Layer w10: H6.1@3924.9,5918.8 3924.9,5909.9 3825,5810 3825,5210 3965.5,5069.5 U3.39
PC9: H3.4 U3.40 | length 1038.3
  Top Layer w10: H3.4 3810,5200 3960.2,5049.8 U3.40
PC10: SW4.C SW4.D SW8.C SW8.D SW12.C SW12.D SW20.C SW20.D U3.51 | length 2725.9
  Top Layer w10: v1(4080,4655) 4095,4655 4180,4740 4180,4814.3 U3.51
  Bottom Layer w10: SW20.C 4080,4226.4 v1(4080,4655) ; SW12.D SW12.C 4095,3443.7 4095,3539.5 SW8.C ; SW8.D SW8.C ; SW4.D SW4.C@4019.5,3890.5 ; SW20.D 4033.6,4156.4 4095,4095 4095,3975.5 SW4.C SW4.C@4019.5,3890.5 ; SW8.C 4085,3699.6 4085,3825 SW4.C@4019.5,3890.5
PC11: SW5.C SW5.D SW9.C SW9.D SW13.C SW13.D SW21.C SW21.D U3.52 | length 2780.8
  Top Layer w10: v1(4145,4565) 4145,4670 4201,4726 U3.52
  Bottom Layer w10: v1(4145,4565) 4145,4345 4333.6,4156.4 SW21.C@4348.6,4156.4 ; SW13.C@4348.6,3358.6 SW13.C@4353.6,3358.6 ; SW13.D@4604.4,3358.6 SW13.C@4353.6,3358.6 ; SW9.D@4604.4,3624.5 SW9.C@4348.6,3624.5 ; SW5.D@4604.4,3890.5 SW5.C@4348.6,3890.5 ; SW21.D@4604.4,4156.4 4368.6,4156.4 4430,4095 4430,3971.9 SW5.C@4348.6,3890.5 ; SW9.C@4348.6,3624.5 4435,3711 4435,3804 SW5.C@4348.6,3890.5 ; SW9.C@4348.6,3624.5 4440,3533.1 4440,3445 SW13.C@4353.6,3358.6
PC12: SW6.C SW6.D SW10.C SW10.D SW14.C SW14.D SW22.C SW22.D U3.53 | length 2973.4
  Top Layer w10: v1(4180,4595) 4180,4675 4220.6,4715.6 U3.53
  Bottom Layer w10: v1(4180,4595) 4500,4275 4625,4275 4687.1,4212.9 SW22.C 4723.6,4156.4 ; SW14.D SW14.C 4760,3431.5 4760,3555 SW10.C@4690.5,3624.5 ; SW10.D SW10.C@4690.5,3624.5 ; SW6.D SW6.C@4699.5,3890.5 ; SW22.D 4723.6,4156.4 ; SW10.C@4690.5,3624.5 SW10.C 4775,3712.4 4775,3815 SW6.C@4699.5,3890.5 ; SW6.C@4699.5,3890.5 SW6.C 4785,3988.3 4785,4095 4723.6,4156.4
PC13: LED1.1 U3.2 | length 329.7
  Top Layer w10: U3.2 4542.9,4912.1 4575,4880 4575,4805 4623,4757 LED1.1
PC14: C15.2 U3.3 X3.2 | length 327.2
  Top Layer w10: U3.3 4598.3,4931.7 4671.7,4858.3 X3.2 4717.5,4900 4740,4900 C15.2
PC15: C16.2 U3.4 X3.1 | length 318.6
  Top Layer w10: U3.4 4596.4,4951.4 4640,4995 4650,4995 4675.8,4969.2 X3.1 4677.1,4960 4757.4,4960 C16.2
PH0: C1.2 U3.5 X5.1 | length 409.3
  Top Layer w10: U3.5 4596.1,4971.1 4635,5010 4745,5010 4778.5,5043.5 X5.1 4787,5058.2 C1.2
PH1: C2.2 U3.6 X5.3 | length 401.6
  Top Layer w10: U3.6 4585.8,4990.8 4660,5065 4660,5150 4667.1,5157.1 4707.8,5157.1 X5.3 4720.5,5162.3 C2.2
VBUS: D1.1 USB1.A4B9 USB1.B4A9 | length 2273.5
  Top Layer w10: v1(3595,4980) 3595,4895 3630,4860 3705,4860 3740,4895 3740,4965 3724.5,4980.5 USB1.B4A9 ; v1(3615,5155) 3618.2,5158.2 3654,5158.2 3665.3,5169.5 USB1.A4B9
  Top Layer w15: v1(4620,5545) 4690.7,5545 D1.1
  PWR w10: v1(3595,4980) 3595,5135 v1(3615,5155)
  Bottom Layer w15: v1(3615,5155) 3805,4965 4270,4965 4375,5070 4375,5140 4415,5180 4565,5180 4620,5235 v1(4620,5545)
VREF+: C7.2 C8.2 L2.2 U3.13 | length 762.9
  Top Layer w10: v1(4405,5120) 4450,5120 4458.6,5128.6 U3.13 ; v1(4650,5355) 4650,5395 4677.8,5422.8 C7.2
  Top Layer w15: C7.2 C8.2 4793.5,5420 L2.2
  PWR w10: v1(4405,5120) 4405,5160 4416.3,5171.3 4456.3,5171.3 4640,5355 v1(4650,5355)
pads on no net: USB1.A8 USB1.B8

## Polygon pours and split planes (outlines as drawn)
GND on Top Layer (solid, remove dead copper, pour order 2): 3205,6260 3205,3090 5960,3090 5960,6260
GND on Bottom Layer (solid, remove dead copper, pour order 4): 3000,6210 3000,3000 5920,3000 5920,6210
GND on PWR (solid, remove dead copper): 3100,6280 3100,3100 6195,3100 6195,6280

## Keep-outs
Board Outline Layer:
  region: 4475,4922 4475,4995 4480.7,5000.7 4582,5000.7 4650,5068.8 4650,5150 4675,5175 4675,5260 4685,5270 4905,5270 4905,4865 4860,4820 4630,4820 4624.5,4825.5 4624.5,4892.5 4595,4922
  lines w10: 3440,3265 3440,5985 5735,5985 5735,3265 3440,3265

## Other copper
Top Layer:
  drawing of 250 lines, arcs and shapes, not listed
PWR:
  region net VBUS: 3607,5139.9 3599.9,5147 3600.9,5148.5 3601.9,5150.7 3602.6,5153.3 3603,5155.8 3615.8,5143 3613.3,5142.6 3610.7,5141.9 3608.5,5140.9
  region net VBUS: 3590,4996.3 3600,4996.3 3600.3,4994.5 3601.3,4992.3 3602.5,4989.9 3604,4987.9 3586,4987.9 3587.5,4989.9 3588.7,4992.3 3589.7,4994.5
  region net 3.3V: 4052.5,4838.7 4037.5,4838.7 4037.4,4841.3 4037,4843.8 4036.5,4845.9 4036,4847.1 4054,4847.1 4053.5,4845.9 4053,4843.8 4052.6,4841.3
  region net 3.3V: 4603.7,4487.5 4603.7,4502.5 4606.3,4502.6 4608.8,4503 4610.9,4503.5 4612.1,4504 4612.1,4486 4610.9,4486.5 4608.8,4487 4606.3,4487.4
  region net 3.3V: 3551,4712.5 3551,4697.5 3546.6,4697.2 3542.4,4696.2 3538.4,4694.5 3534.7,4692.3 3531.3,4689.5 3528.5,4686.3 3528.5,4723.8 3531.3,4720.5 3534.7,4717.7 3538.4,4715.5 3542.4,4713.8 3546.6,4712.8 3551,4712.5
  region net 3.3V: 4028.7,4847.5 4028.7,4862.5 4031.3,4862.6 4033.8,4863 4035.9,4863.5 4037.1,4864 4037.1,4846 4035.9,4846.5 4033.8,4847 4031.3,4847.4
  region net VREF+: 4400,5136.3 4410,5136.3 4410.3,5134.5 4411.3,5132.3 4412.5,5129.9 4414,5127.9 4396,5127.9 4397.5,5129.9 4398.7,5132.3 4399.7,5134.5
  region net 3.3V: 3934.9,5343 3942,5350.1 3943.5,5349.1 3945.7,5348.1 3948.3,5347.4 3950.8,5347 3938,5334.2 3937.6,5336.7 3936.9,5339.3 3935.9,5341.5
  region net 3.3V: 3548.4,5514.3 3548.4,5504.3 3544.9,5504 3541.6,5503.1 3538.5,5501.5 3535.7,5499.4 3533.4,5496.8 3533.4,5521.8 3535.7,5519.3 3538.5,5517.2 3541.6,5515.6 3544.9,5514.7 3548.4,5514.3
  region net 3.3V: 3770.7,5544.3 3770.3,5539.6 3769.2,5535.1 3767.4,5530.7 3764.9,5526.7 3761.9,5523.1 3758.3,5520.1 3754.3,5517.6 3749.9,5515.8 3745.4,5514.7 3740.7,5514.3 3743.6,5504.3 3750.7,5504 3757.7,5502.9 3764.6,5501.2 3771.3,5498.8 3777.7,5495.8 3783.8,5492.1 3789.5,5487.9 3794.8,5483.1 3801.9,5490.2 3797.1,5495.5 3792.9,5501.2 3789.2,5507.3 3786.2,5513.7 3783.8,5520.4 3782.1,5527.3 3781,5534.3 3780.7,5541.4
  region net 3.3V: 3645.8,5891.3 3638.7,5884.2 3635.9,5884.6 3628.9,5885.2 3607.9,5886.6 3643.4,5922.1 3644.8,5901.1 3645.4,5894.1
  region net 3.3V: 4418.1,5327.5 4418.1,5342.5 4420.7,5342.6 4423.3,5343 4425.3,5343.5 4426.5,5344 4426.5,5326 4425.3,5326.5 4423.3,5327 4420.7,5327.4
  region net 3.3V: 3966.3,5342.5 3966.3,5327.5 3963.7,5327.4 3961.2,5327 3959.1,5326.5 3957.9,5326 3957.9,5344 3959.1,5343.5 3961.2,5343 3963.7,5342.6
  region net 3.3V: 4440.7,5351.9 4451.3,5341.3 4449.6,5339.3 4448,5337.3 4446.9,5335.5 4446.4,5334.2 4433.7,5347 4435,5347.4 4436.8,5348.6 4438.8,5350.1
  region net 3.3V: 4061.3,4862.5 4061.3,4847.5 4058.7,4847.4 4056.2,4847 4054.1,4846.5 4052.9,4846 4052.9,4864 4054.1,4863.5 4056.2,4863 4058.7,4862.6
  region net 3.3V: 4428.2,5318.1 4417.6,5328.7 4419.4,5330.7 4420.9,5332.7 4422,5334.5 4422.5,5335.8 4435.2,5323 4434,5322.6 4432.2,5321.4 4430.1,5319.9
  region net 3.3V: 4692.5,5459.6 4677.5,5463.2 4677.3,5468.7 4677.2,5470.6 4677,5471.6 4694.6,5468 4694.2,5467.6 4693.9,5466.8 4693.2,5464.8 4692.7,5462.3
  region net 5V: 5337.3,5421.9 5323.1,5407.7 5321.5,5409.2 5319.9,5410.5 5316.6,5412.9 5313.6,5414.8 5311.5,5416.5 5328.5,5433.5 5330.2,5431.4 5332.1,5428.4 5334.5,5425.1 5335.8,5423.5
  region net 3.3V: 5629.4,5087.5 5629.4,5102.5 5630.5,5102.9 5632.4,5104 5638.1,5108 5645.2,5113.6 5652.9,5120.1 5652.9,5069.9 5645.2,5076.4 5638.1,5082 5632.4,5086 5630.5,5087.1
  region net 3.3V: 5131.3,5612.5 5131.3,5597.5 5128.7,5597.4 5126.2,5597 5124.1,5596.5 5122.9,5596 5122.9,5614 5124.1,5613.5 5126.2,5613 5128.7,5612.6
  region net 5V: 5604.5,4872.2 5604.5,4892.2 5609.4,4892.5 5614.3,4893.5 5619,4895.1 5623.4,4897.3 5627.5,4900.1 5631.2,4903.4 5634.5,4907.2 5634.5,4857.2 5631.2,4861 5627.5,4864.3 5623.4,4867.1 5619,4869.3 5614.3,4870.9 5609.4,4871.9 5604.5,4872.2
  region net 3.3V: 5121.3,5621.9 5131.9,5611.3 5130.1,5609.3 5128.6,5607.3 5127.4,5605.5 5127,5604.2 5114.2,5617 5115.5,5617.4 5117.3,5618.6 5119.3,5620.1
  region net 3.3V: 5532.5,5875.8 5517.5,5875.8 5517.1,5876.9 5516.1,5878.8 5512.2,5884.2 5506.8,5891.2 5500.6,5898.5 5549.4,5898.5 5543.2,5891.2 5537.8,5884.2 5533.9,5878.8 5532.9,5876.9
Bottom Layer:
  region net VBUS: 3631.9,5148.7 3621.3,5138.1 3619.3,5139.9 3617.3,5141.4 3615.5,5142.6 3614.2,5143 3627,5155.8 3627.4,5154.5 3628.6,5152.7 3630.1,5150.7
  region net 5V: 5239,5451 5209.7,5442.8 5213.6,5447.2 5216.9,5452.1 5219.5,5457.3 5221.5,5462.8 5259,5462.8 5253.5,5460.8 5248.3,5458.1 5243.4,5454.8 5239,5451
  region net VBUS: 4627.5,5528.7 4612.5,5528.7 4612.4,5531.3 4612,5533.8 4611.5,5535.9 4611,5537.1 4629,5537.1 4628.5,5535.9 4628,5533.8 4627.6,5531.3
  region net 5V: 4937.5,5528.7 4922.5,5528.7 4922.4,5531.3 4922,5533.8 4921.5,5535.9 4921,5537.1 4939,5537.1 4938.5,5535.9 4938,5533.8 4937.6,5531.3
  region net 3.3V: 5094.7,5590.3 5105.3,5579.7 5104.2,5577.4 5103.7,5574.9 5103.9,5572.4 5104.8,5570 5106.3,5567.9 5108.3,5566.3 5110.6,5565.3 5113.1,5565 5070,5555 5046.9,5565 5054.5,5566.8 5062,5569.2 5069.2,5572.3 5076.1,5576 5082.7,5580.2 5088.9,5585 5094.7,5590.3
  region net 3.3V: 5108.7,5588.1 5098.1,5598.7 5099.9,5600.7 5101.4,5602.7 5102.6,5604.5 5103,5605.8 5115.8,5593 5114.5,5592.6 5112.7,5591.4 5110.7,5589.9
  region net 3.3V: 5085,5585 5085,5565 5082,5563.7 5079.3,5561.7 5077.1,5559.3 5075.5,5556.4 5074.5,5553.3 5074.1,5550 5074.1,5600 5074.5,5596.7 5075.5,5593.6 5077.1,5590.7 5079.3,5588.3 5082,5586.3
  region net 3.3V: 5182.7,5565 5182.7,5585 5188.2,5585.3 5193.6,5586.3 5198.8,5588 5203.8,5590.3 5208.4,5593.2 5212.7,5596.7 5212.7,5553.3 5208.4,5556.8 5203.8,5559.7 5198.8,5562 5193.6,5563.7 5188.2,5564.7 5182.7,5565
  region net PA15: 3714.3,3895.5 3714.3,3885.5 3712.1,3883.9 3707,3879.6 3692.2,3866.8 3692.2,3914.1 3707,3901.3 3712.1,3897.1
  region net PA15: 3884.4,3885.5 3884.4,3895.5 3886.6,3897.1 3891.7,3901.3 3906.5,3914.1 3906.5,3866.8 3891.7,3879.6 3886.6,3883.9
  region net PA15: 3698.2,3924.3 3705.3,3917.2 3704.9,3914.6 3704.2,3908 3702.8,3888.5 3669.4,3921.9 3688.9,3923.3 3695.5,3923.9
  region net PA15: 3705.3,3863.7 3698.2,3856.6 3695.5,3857 3688.9,3857.6 3669.4,3859 3702.8,3892.4 3704.2,3872.9 3704.9,3866.3
  region net PA15: 3706.9,4145.2 3712.2,4125.7 3711.4,4126.4 3710.2,4127 3707.4,4128 3703.8,4128.7 3699.7,4129 3695.3,4128.9 3690.7,4128.5 3686.2,4127.7 3681.9,4126.5 3700.5,4169.9 3701.2,4167.8 3701.6,4165 3702.2,4158.1 3702.7,4154.5 3703.6,4151 3704.2,4149.4 3704.9,4147.8 3705.8,4146.4
  region net PA15: 3698.2,3658.4 3705.3,3651.3 3704.9,3648.7 3704.2,3642.1 3702.8,3622.6 3669.4,3656 3688.9,3657.4 3695.5,3658
  region net PA15: 3714.9,4161.4 3714.9,4151.4 3712.8,4149.8 3707.7,4145.6 3692.9,4132.8 3692.9,4180 3707.7,4167.2 3712.8,4163
  region net PA15: 3885.1,4151.4 3885.1,4161.4 3887.2,4163 3892.3,4167.2 3907.1,4180 3907.1,4132.8 3892.3,4145.6 3887.2,4149.8
  region net PA15: 3706.2,3615.9 3713.4,3594.5 3712.5,3595.3 3711.2,3596 3709.8,3596.6 3708.2,3597.2 3704.6,3597.9 3700.5,3598.2 3696.1,3598.1 3691.6,3597.6 3687.2,3596.7 3683.1,3595.3 3699,3639.8 3699.7,3637.8 3700.2,3635.1 3701.2,3628.5 3701.8,3625 3702.8,3621.6 3703.4,3620 3704.2,3618.5 3705.1,3617.1
  region net PA15: 3714.3,3629.5 3714.3,3619.5 3712.1,3617.9 3707,3613.7 3692.2,3600.9 3692.2,3648.2 3707,3635.4 3712.1,3631.1
  region net PA15: 3884.4,3619.5 3884.4,3629.5 3886.6,3631.1 3891.7,3635.4 3906.5,3648.2 3906.5,3600.9 3891.7,3613.7 3886.6,3617.9
  region net PA15: 3698.2,3392.5 3705.3,3385.4 3704.9,3382.8 3704.2,3376.2 3702.8,3356.7 3669.4,3390.1 3688.9,3391.5 3695.5,3392.1
  region net PA15: 3714.3,3363.6 3714.3,3353.6 3712.1,3352 3707,3347.8 3692.2,3335 3692.2,3382.3 3707,3369.5 3712.1,3365.2
  region net PA15: 3884.4,3353.6 3884.4,3363.6 3886.6,3365.2 3891.7,3369.5 3906.5,3382.3 3906.5,3335 3891.7,3347.8 3886.6,3352
  region net PC10: 4052.9,3895.5 4052.9,3885.5 4050.7,3883.9 4045.6,3879.6 4030.8,3866.8 4030.8,3914.1 4045.6,3901.3 4050.7,3897.1
  region net PC10: 4223,3885.5 4223,3895.5 4225.1,3897.1 4230.2,3901.3 4245,3914.1 4245,3866.8 4230.2,3879.6 4225.1,3883.9
  region net PC10: 4036.8,3924.3 4043.8,3917.2 4043.4,3914.6 4042.8,3908 4041.4,3888.5 4008,3921.9 4027.5,3923.3 4034.1,3923.9
  region net PC10: 4044.7,3872.4 4044.8,3858.1 4044.2,3858.6 4043.3,3859 4040.8,3859.7 4037.5,3860.1 4033.5,3860.4 4029.1,3860.5 4024.4,3860.3 4019.6,3859.9 4014.8,3859.3 4040.2,3899.1 4040.6,3896.7 4040.7,3893.6 4040.7,3886.1 4040.9,3882.2 4041.6,3878.5 4042.1,3876.7 4042.8,3875.1 4043.6,3873.7
  region net PC10: 4044.5,4152.5 4055.2,4127.7 4054.1,4128.7 4052.7,4129.6 4051.1,4130.3 4049.5,4131 4045.7,4131.9 4041.6,4132.2 4037.2,4132.1 4032.9,4131.5 4028.8,4130.3 4026.8,4129.6 4025,4128.7 4035.6,4174.7 4036.5,4172.9 4037.3,4170.5 4038.8,4164.5 4039.7,4161.3 4040.9,4158.1 4042.5,4155.1 4043.4,4153.8
  region net PC10: 4036.8,3658.4 4043.8,3651.3 4043.4,3648.7 4042.8,3642.1 4041.4,3622.6 4008,3656 4027.5,3657.4 4034.1,3658
  region net PC10: 4052.9,4161.4 4052.9,4151.4 4050.7,4149.8 4045.6,4145.5 4030.8,4132.7 4030.8,4180 4045.6,4167.2 4050.7,4163
  region net PC10: 4223,4151.4 4223,4161.4 4225.1,4163 4230.2,4167.2 4245,4180 4245,4132.7 4230.2,4145.5 4225.1,4149.8
  region net PC10: 4052.9,3629.5 4052.9,3619.5 4050.7,3617.9 4045.6,3613.7 4030.8,3600.9 4030.8,3648.2 4045.6,3635.4 4050.7,3631.1
  region net PC10: 4223,3619.5 4223,3629.5 4225.1,3631.1 4230.2,3635.4 4245,3648.2 4245,3600.9 4230.2,3613.7 4225.1,3617.9
  region net PC10: 4043.8,3597.8 4036.8,3590.7 4034.1,3591.1 4027.5,3591.7 4008,3593.1 4041.4,3626.5 4042.8,3607 4043.4,3600.4
  region net PC10: 4036.8,3392.5 4043.8,3385.4 4043.4,3382.8 4042.8,3376.2 4041.4,3356.7 4008,3390.1 4027.5,3391.5 4034.1,3392.1
  region net PC10: 4052.9,3363.6 4052.9,3353.6 4050.7,3352 4045.6,3347.8 4030.8,3335 4030.8,3382.3 4045.6,3369.5 4050.7,3365.2
  region net PC10: 4223,3353.6 4223,3363.6 4225.1,3365.2 4230.2,3369.5 4245,3382.3 4245,3335 4230.2,3347.8 4225.1,3352
  region net PC11: 4391.4,3895.5 4391.4,3885.5 4389.3,3883.9 4384.2,3879.6 4369.4,3866.8 4369.4,3914.1 4384.2,3901.3 4389.3,3897.1
  region net PC11: 4561.6,3885.5 4561.6,3895.5 4563.7,3897.1 4568.8,3901.3 4583.6,3914.1 4583.6,3866.8 4568.8,3879.6 4563.7,3883.9
  region net PC11: 4375.3,3924.3 4382.4,3917.2 4382,3914.6 4381.4,3908 4380,3888.5 4346.6,3921.9 4366.1,3923.3 4372.7,3923.9
  region net PC11: 4382.4,3863.7 4375.3,3856.6 4372.7,3857 4366.1,3857.6 4346.6,3859 4380,3892.4 4381.4,3872.9 4382,3866.3
  region net PC11: 4383.3,4148.7 4391.3,4126.6 4390.3,4127.5 4389.1,4128.2 4387.6,4128.9 4386,4129.4 4382.3,4130.2 4378.2,4130.5 4373.8,4130.4 4369.4,4129.8 4365,4128.9 4361,4127.4 4375.7,4172.3 4376.5,4170.3 4377.1,4167.7 4378.1,4161.3 4378.8,4157.8 4379.9,4154.4 4380.5,4152.9 4381.3,4151.4 4382.2,4150
  region net PC11: 4375.3,3658.4 4382.4,3651.3 4382,3648.7 4381.4,3642.1 4380,3622.6 4346.6,3656 4366.1,3657.4 4372.7,3658
  region net PC11: 4391.4,4161.4 4391.4,4151.4 4389.3,4149.8 4384.2,4145.5 4369.4,4132.7 4369.4,4180 4384.2,4167.2 4389.3,4163
  region net PC11: 4561.6,4151.4 4561.6,4161.4 4563.7,4163 4568.8,4167.2 4583.6,4180 4583.6,4132.7 4568.8,4145.5 4563.7,4149.8
  region net PC11: 4382.4,3597.8 4375.3,3590.7 4372.7,3591.1 4366.1,3591.7 4346.6,3593.1 4380,3626.5 4381.4,3607 4382,3600.4
  region net PC11: 4391.4,3629.5 4391.4,3619.5 4389.3,3617.9 4384.2,3613.7 4369.4,3600.9 4369.4,3648.2 4384.2,3635.4 4389.3,3631.1
  region net PC11: 4561.6,3619.5 4561.6,3629.5 4563.7,3631.1 4568.8,3635.4 4583.6,3648.2 4583.6,3600.9 4568.8,3613.7 4563.7,3617.9
  region net PC11: 4379.7,3391.8 4382.9,3380.9 4381.9,3379.6 4381.1,3378.1 4380.4,3376.5 4379.9,3374.7 4379.4,3370.8 4379.3,3366.7 4379.6,3358.9 4379.7,3355.6 4379.6,3353.1 4350.2,3390.1 4360.2,3389.9 4369.3,3390.1 4373.2,3390.4 4376.3,3390.8 4378.5,3391.2
  region net PC11: 4391.4,3363.6 4391.4,3353.6 4389.3,3352 4384.2,3347.8 4369.4,3335 4369.4,3382.3 4384.2,3369.5 4389.3,3365.2
  region net PC11: 4561.6,3353.6 4561.6,3363.6 4563.7,3365.2 4568.8,3369.5 4583.6,3382.3 4583.6,3335 4568.8,3347.8 4563.7,3352
  region net PC12: 4730,3895.5 4730,3885.5 4727.9,3883.9 4722.8,3879.6 4708,3866.8 4708,3914.1 4722.8,3901.3 4727.9,3897.1
  region net PC12: 4900.1,3885.5 4900.1,3895.5 4902.3,3897.1 4907.4,3901.3 4922.2,3914.1 4922.2,3866.8 4907.4,3879.6 4902.3,3883.9
  region net PC12: 4722,3875.1 4724.2,3858.7 4723.5,3859.3 4722.5,3859.8 4719.8,3860.6 4716.4,3861.1 4712.4,3861.4 4708,3861.4 4703.3,3861.1 4698.6,3860.6 4694,3859.7 4716.8,3901.1 4717.2,3898.8 4717.5,3895.8 4717.7,3888.6 4718,3884.8 4718.8,3881.1 4719.3,3879.4 4720,3877.8 4720.9,3876.4
  region net PC12: 4713.9,3924.3 4721,3917.2 4720.6,3914.6 4720,3908 4718.6,3888.5 4685.2,3921.9 4704.7,3923.3 4711.3,3923.9
  region net PC12: 4713.9,3658.4 4721,3651.3 4720.6,3648.7 4720,3642.1 4718.6,3622.6 4685.2,3656 4704.7,3657.4 4711.3,3658
  region net PC12: 4742.8,4130.1 4737.2,4135.3 4731.3,4140 4725,4144.3 4718.4,4148.1 4711.6,4151.4 4723.6,4156.4 4745.7,4151.4 4746.9,4146.6 4748.6,4142.1 4750.9,4137.8 4753.7,4133.8 4756.9,4130.1 4742.8,4130.1
  region net PC12: 4721.4,3600.7 4716.8,3591.1 4715.8,3591.6 4713.6,3591.9 4706.8,3592.6 4697.6,3593 4687.5,3593.1 4718.3,3628.9 4718.4,3626.3 4718.3,3623 4717.8,3615 4717.9,3610.9 4718.4,3607 4718.8,3605.1 4719.5,3603.5 4720.3,3602
  region net PC12: 4730,3629.5 4730,3619.5 4727.9,3617.9 4722.8,3613.7 4708,3600.9 4708,3648.2 4722.8,3635.4 4727.9,3631.1
  region net PC12: 4900.1,3619.5 4900.1,3629.5 4902.3,3631.1 4907.4,3635.4 4922.2,3648.2 4922.2,3600.9 4907.4,3613.7 4902.3,3617.9
  region net PC12: 4723.6,4161.4 4723.6,4151.4 4722.5,4151.2 4721.3,4150.7 4720.2,4149.9 4719.1,4148.9 4716.9,4146.3 4714.8,4143.3 4711.1,4137 4709.4,4134.5 4708,4132.7 4708,4180 4709.4,4178.3 4711.1,4175.7 4714.8,4169.5 4716.9,4166.4 4719.1,4163.8 4720.2,4162.8 4721.3,4162 4722.5,4161.5
  region net PC12: 4900.1,4151.4 4900.1,4161.4 4902.3,4163 4907.4,4167.2 4922.2,4180 4922.2,4132.7 4907.4,4145.5 4902.3,4149.8
  region net PC12: 4713.9,3392.5 4721,3385.4 4720.6,3382.8 4720,3376.2 4718.6,3356.7 4685.2,3390.1 4704.7,3391.5 4711.3,3392.1
  region net PC12: 4730,3363.6 4730,3353.6 4727.9,3352 4722.8,3347.8 4708,3335 4708,3382.3 4722.8,3369.5 4727.9,3365.2
  region net PC12: 4900.1,3353.6 4900.1,3363.6 4902.3,3365.2 4907.4,3369.5 4922.2,3382.3 4922.2,3335 4907.4,3347.8 4902.3,3352
  region net PA15: 3894.1,4183.2 3901.2,4190.3 3903.8,4189.9 3910.4,4189.3 3929.9,4187.9 3896.5,4154.4 3895.1,4174 3894.5,4180.5
  region net PA15: 4053.9,4676.9 4046.9,4683.9 4047.9,4685.5 4048.9,4687.7 4049.6,4690.3 4050,4692.7 4062.7,4680 4060.3,4679.6 4057.7,4678.9 4055.5,4677.9
  region net PC10: 4036.8,4190.2 4043.8,4183.1 4043.4,4180.5 4042.8,4173.9 4041.4,4154.4 4008,4187.8 4027.5,4189.2 4034.1,4189.8
  region net PC10: 4085,4638.7 4075,4638.7 4074.7,4640.5 4073.7,4642.7 4072.5,4645.1 4071,4647.1 4089,4647.1 4087.5,4645.1 4086.3,4642.7 4085.3,4640.5
  region net PC11: 4150,4548.7 4140,4548.7 4139.7,4550.5 4138.7,4552.7 4137.5,4555.1 4136,4557.1 4154,4557.1 4152.5,4555.1 4151.3,4552.7 4150.3,4550.5
  region net PC11: 4313.7,4169.2 4309.6,4187.5 4310.4,4186.8 4311.5,4186.3 4314.3,4185.3 4317.8,4184.7 4321.8,4184.5 4326.2,4184.5 4330.8,4184.9 4335.4,4185.6 4339.9,4186.6 4319.6,4144 4319,4146.2 4318.7,4149.1 4318.2,4156.1 4317.8,4159.8 4316.9,4163.3 4316.4,4165 4315.6,4166.6 4314.8,4168
  region net PC12: 4195.1,4587 4188,4579.9 4186.5,4580.9 4184.3,4581.9 4181.7,4582.6 4179.2,4583 4192,4595.8 4192.4,4593.3 4193.1,4590.7 4194.1,4588.5
  region net PC12: 4682.1,4199.2 4692.1,4199.2 4693.7,4197.1 4697.9,4192 4710.7,4177.2 4663.5,4177.2 4676.3,4192 4680.5,4197.1
  region net PC0: 5629.4,5190 5629.4,5200 5631.6,5201.7 5637,5206.3 5652.9,5220.1 5652.9,5169.9 5637,5183.7 5631.6,5188.3

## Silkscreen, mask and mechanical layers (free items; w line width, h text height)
Top Silkscreen Layer:
  text "3.3V" at 3580,5830 h35
  text "SCL" at 3680,5830 h35
  text "SDA" at 3780,5830 h35
  text "PC8" at 3895,5830 h35
  text "PC7" at 3995,5830 h35
  text "PC6" at 4095,5830 h35
  text "PB15" at 4190,5830 h35
  text "PB14" at 4290,5830 h35
  text "PB13" at 4390,5830 h35
  text "PB12" at 4495,5830 h35
  text "PB10" at 4595,5830 h35
  text "PB1" at 4695,5830 h35
  text "PB0" at 4795,5830 h35
  text "PC5" at 4895,5830 h35
  text "PC4" at 4995,5830 h35
  text "PA7" at 5090,5830 h35
  text "PA6" at 5195,5830 h35
  text "PA5" at 5295,5830 h35
  text "PA4" at 5385,5825 h35
  text "PA9" at 3565,5785 h35
  text "PA3" at 5610,5755 h35 r90
  text "PA10" at 3565,5685 h35
  text "PA2" at 5610,5660 h35 r90
  text "GND" at 3565,5585 h35
  text "PA1" at 5610,5570 h35 r90
  text "3.3V" at 3565,5490 h35
  text "PC3" at 5610,5470 h35 r90
  text "PC2" at 5615,5365 h35 r90
  text "PC1" at 5610,5270 h35 r90
  text "PC0" at 5610,5165 h35 r90
  text "NRST" at 5445,5100 h60 r90
  text "3.3V" at 5615,5065 h35 r90
  text "GND" at 5614.6,4965 h35 r90
  text "5V" at 5610,4850 h35 r90
  text "GND" at 5610,4755 h35 r90
  text "3.3V" at 3565,4740 h35 r270
  text "用户按键" at 5455,4715 h60 r90
  text "DIO" at 3560,4630 h35 r270
  text "CLK" at 3565,4535 h35 r270
  text "GND" at 3565,4435 h35 r270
